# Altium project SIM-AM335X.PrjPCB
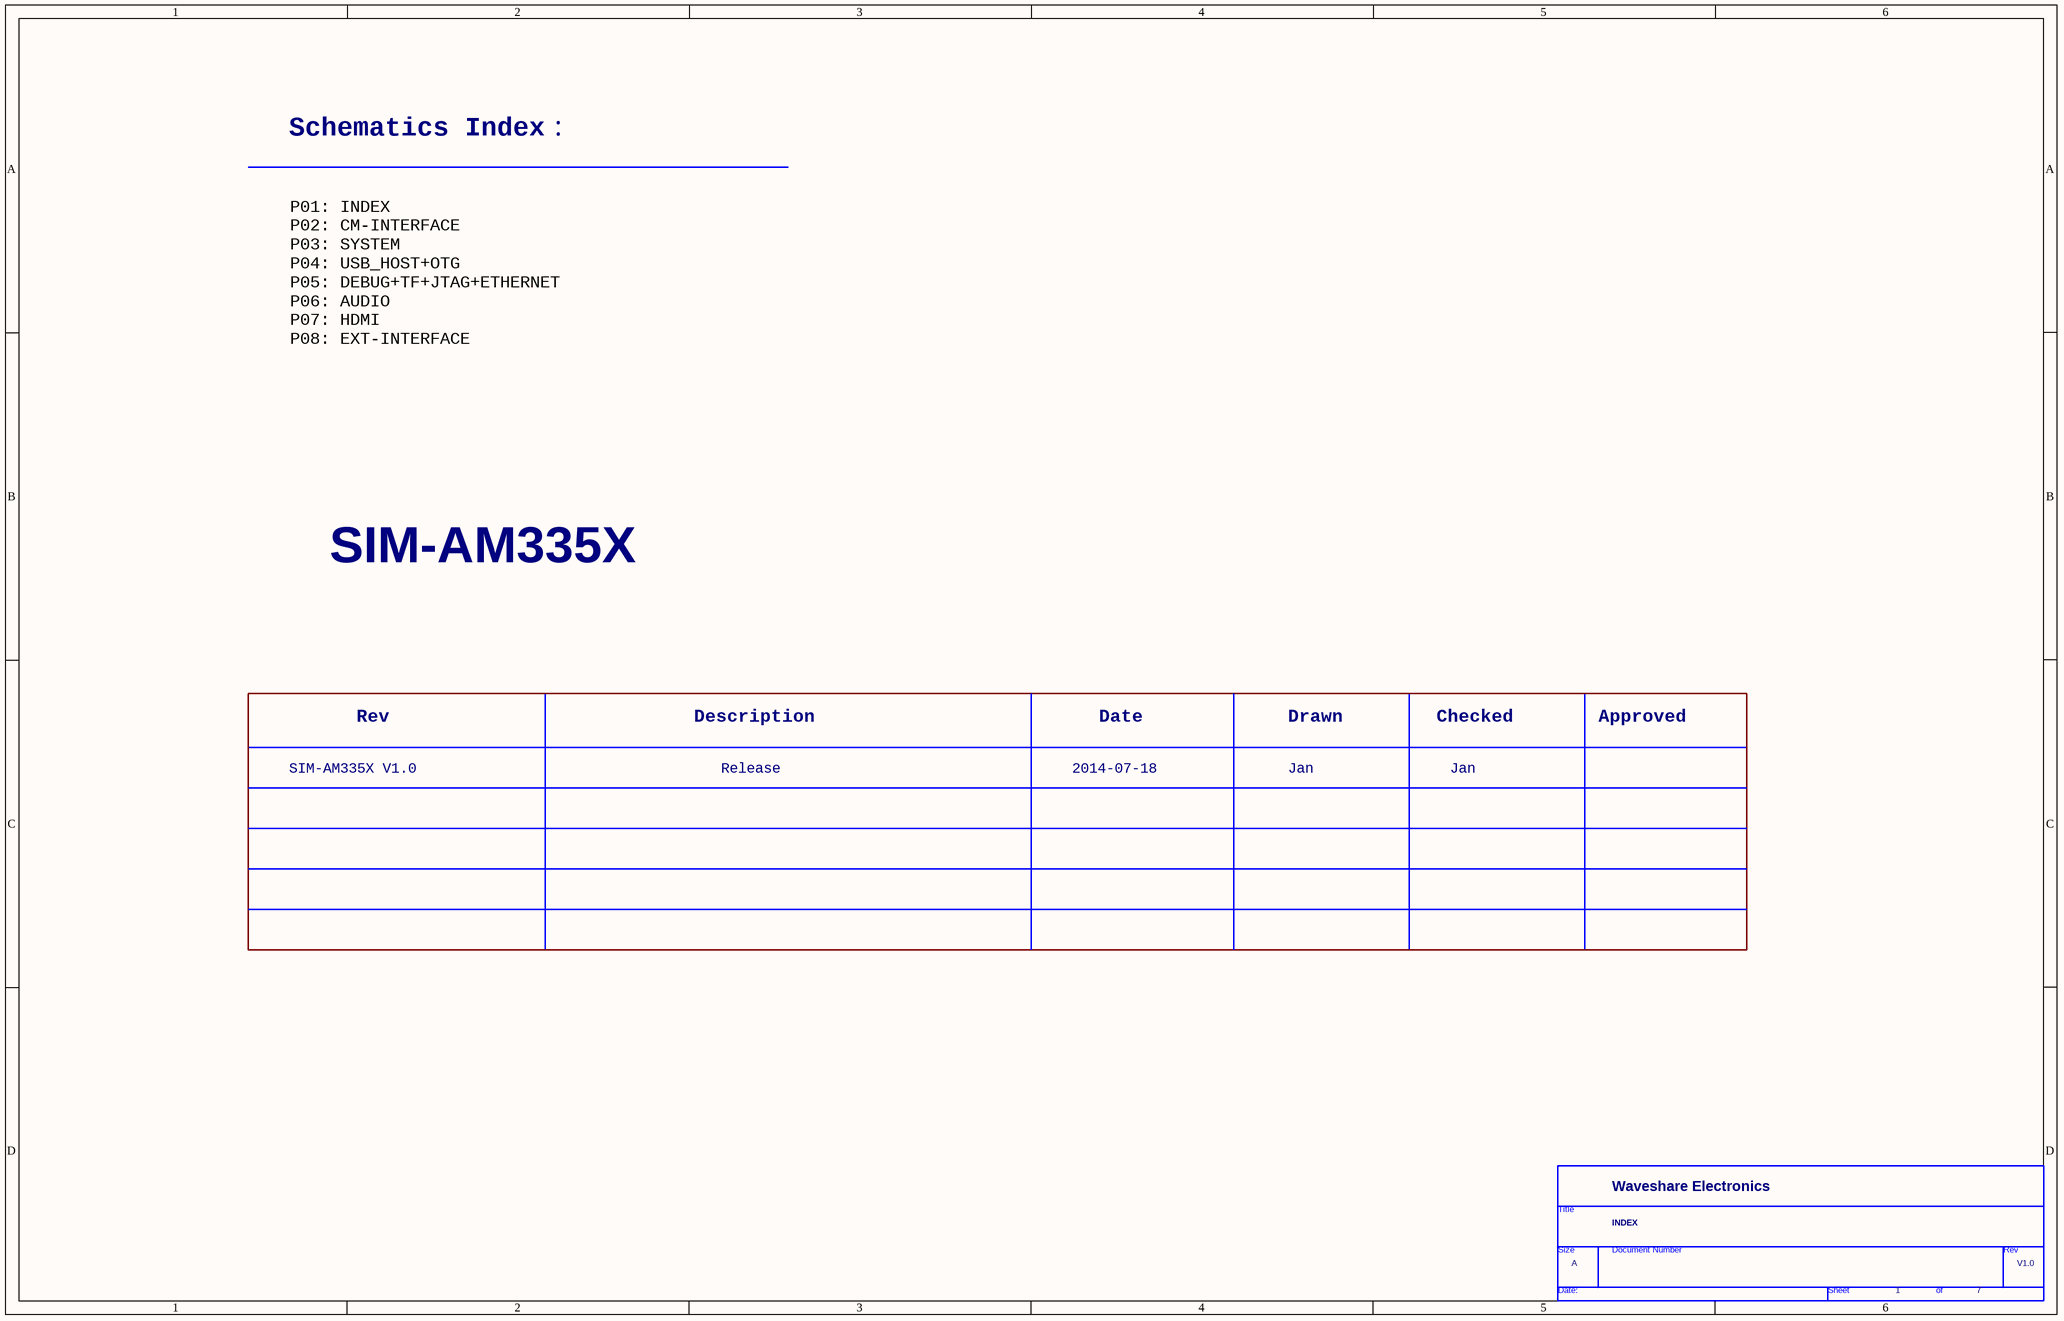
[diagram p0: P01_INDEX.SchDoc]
7 sheets, 179 parts. Net scope: global (net labels, ports and power ports of the same name join across sheets).
Board file: SIM-AM335X.PcbDoc
Sheets:
  P01_INDEX.SchDoc
  P02_CM-INTERFACE.SchDoc
  P03_SYSTEM.SchDoc
  P04_DEBUG+TF.SchDoc
  P05_USB_HOST+OTG.SchDoc
  P06_HDMI.SchDoc
  P07_EXT-INTERFACE.SchDoc

## Sheet P01_INDEX.SchDoc
size 386 x 246 mm

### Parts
(Parts that share a designator on the sheet are numbered #1, #2 ... from top to bottom, then left to right.)
*#1  Page Count: 7  Page Number: 1  Page Size: A  OrgName: Waveshare Electronics  Title: INDEX  RevCode: V1.0  (hidden comment: TitleBlock1)  (graphical)

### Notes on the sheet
- Schematics Index：
- P01: INDEX
  P02: CM-INTERFACE
  P03: SYSTEM
  P04: USB_HOST+OTG
  P05: DEBUG+TF+JTAG+ETHERNET
  P06: AUDIO
  P07: HDMI
  P08: EXT-INTERFACE
- SIM-AM335X
- Rev
- Description
- Date
- Drawn
- Checked
- Approved
- SIM-AM335X V1.0
- Release
- 2014-07-18
- Jan

## Sheet P02_CM-INTERFACE.SchDoc
size 386 x 246 mm
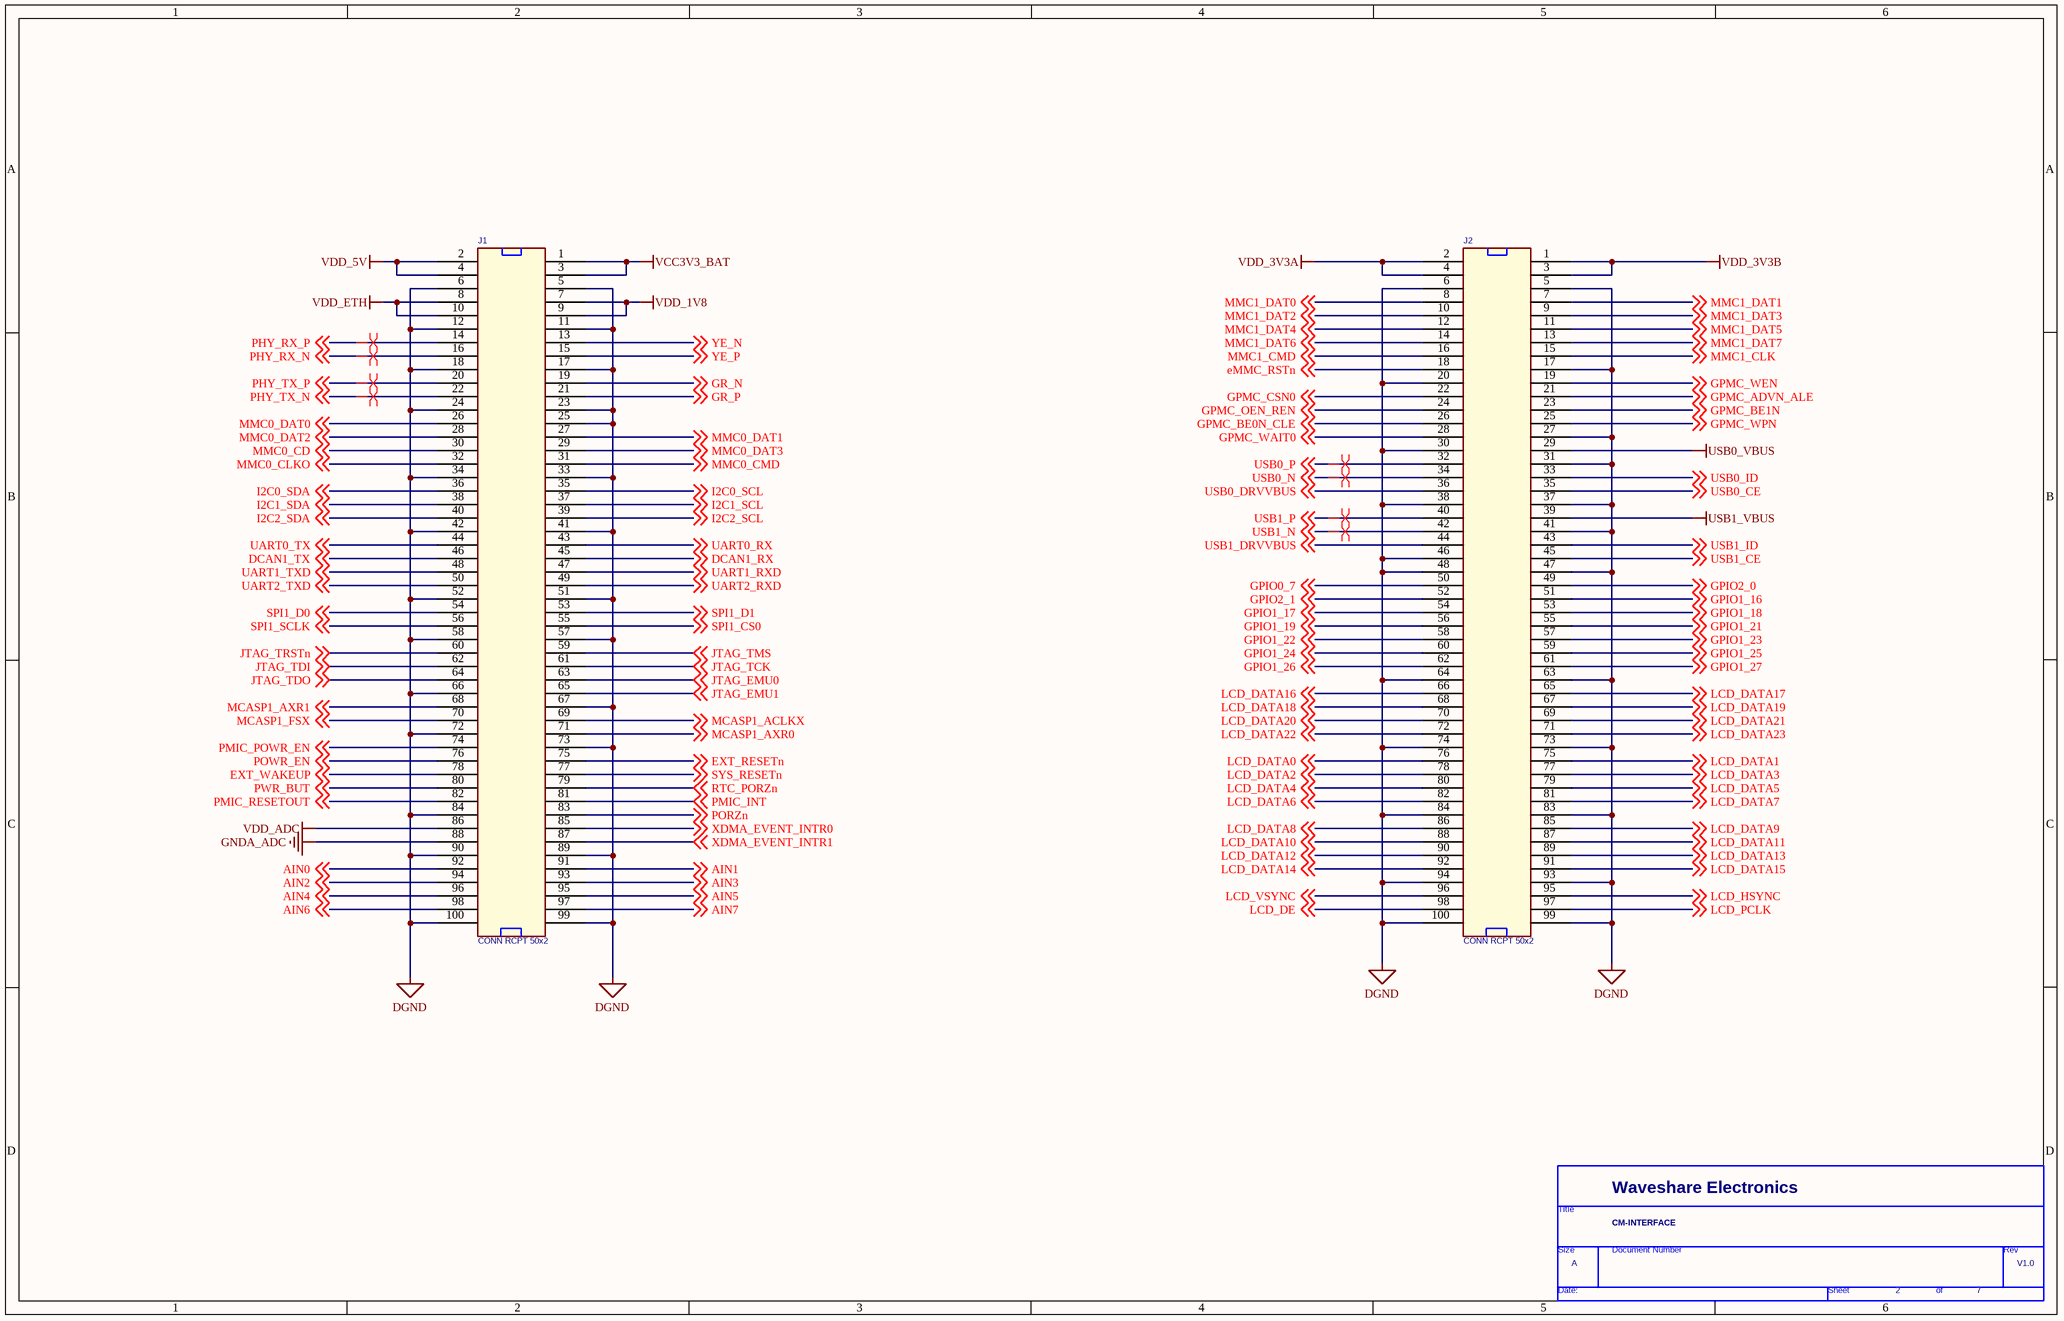
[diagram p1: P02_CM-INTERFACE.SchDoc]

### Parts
(Parts that share a designator on the sheet are numbered #1, #2 ... from top to bottom, then left to right.)
*#2  Page Count: 7  Page Number: 2  Page Size: A  OrgName: Waveshare Electronics  Title: CM-INTERFACE  RevCode: V1.0  (hidden comment: TitleBlock1)  (graphical)
J1  CONN RCPT 50x2  [SMD50X2A-1.27MM_1]
J2  CONN RCPT 50x2  [SMD50X2A-1.27MM_1]

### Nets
DGND: J1.5 J1.6 J1.11 J1.12 J1.17 J1.18 J1.23 J1.24 J1.25 J1.33 J1.34 J1.41 J1.42 J1.51 J1.52 J1.57 J1.58 J1.66 J1.67 J1.72 J1.73 J1.84 J1.89 J1.90 J1.99 J1.100 J2.5 J2.6 J2.17 J2.20 J2.27 J2.30 J2.31 J2.37 J2.38 J2.41 J2.46 J2.47 J2.48 J2.63 J2.64 J2.73 J2.74 J2.83 J2.84 J2.93 J2.94 J2.99 J2.100
GNDA_ADC: J1.88
USB0_VBUS: J2.29
USB1_VBUS: J2.39
VCC3V3_BAT: J1.1 J1.3
VDD_1V8: J1.7 J1.9
VDD_3V3A: J2.2 J2.4
VDD_3V3B: J2.1 J2.3
VDD_5V: J1.2 J1.4
VDD_ADC: J1.86
VDD_ETH: J1.8 J1.10
AIN0: J1.92 ; off-sheet AIN0
AIN1: J1.91 ; off-sheet AIN1
AIN2: J1.94 ; off-sheet AIN2
AIN3: J1.93 ; off-sheet AIN3
AIN4: J1.96 ; off-sheet AIN4
AIN5: J1.95 ; off-sheet AIN5
AIN6: J1.98 ; off-sheet AIN6
AIN7: J1.97 ; off-sheet AIN7
DCAN1_RX: J1.45 ; off-sheet DCAN1_RX
DCAN1_TX: J1.46 ; off-sheet DCAN1_TX
eMMC_RSTn: J2.18 ; off-sheet eMMC_RSTn
EXT_RESETn: J1.75 ; off-sheet EXT_RESETn
EXT_WAKEUP: J1.78 ; off-sheet EXT_WAKEUP
GPIO0_7: J2.50 ; off-sheet GPIO0_7
GPIO1_16: J2.51 ; off-sheet GPIO1_16
GPIO1_17: J2.54 ; off-sheet GPIO1_17
GPIO1_18: J2.53 ; off-sheet GPIO1_18
GPIO1_19: J2.56 ; off-sheet GPIO1_19
GPIO1_21: J2.55 ; off-sheet GPIO1_21
GPIO1_22: J2.58 ; off-sheet GPIO1_22
GPIO1_23: J2.57 ; off-sheet GPIO1_23
GPIO1_24: J2.60 ; off-sheet GPIO1_24
GPIO1_25: J2.59 ; off-sheet GPIO1_25  [project net HDMI_INT]
GPIO1_26: J2.62 ; off-sheet GPIO1_26
GPIO1_27: J2.61 ; off-sheet GPIO1_27
GPIO2_0: J2.49 ; off-sheet GPIO2_0
GPIO2_1: J2.52 ; off-sheet GPIO2_1
GPMC_ADVN_ALE: J2.21 ; off-sheet GPMC_ADVN_ALE
GPMC_BE0N_CLE: J2.26 ; off-sheet GPMC_BE0N_CLE
GPMC_BE1N: J2.23 ; off-sheet GPMC_BE1N
GPMC_CSN0: J2.22 ; off-sheet GPMC_CSN0
GPMC_OEN_REN: J2.24 ; off-sheet GPMC_OEN_REN
GPMC_WAIT0: J2.28 ; off-sheet GPMC_WAIT0
GPMC_WEN: J2.19 ; off-sheet GPMC_WEN
GPMC_WPN: J2.25 ; off-sheet GPMC_WPN
GR_N: J1.19 ; off-sheet GR_N
GR_P: J1.21 ; off-sheet GR_P
I2C0_SCL: J1.35 ; off-sheet I2C0_SCL
I2C0_SDA: J1.36 ; off-sheet I2C0_SDA
I2C1_SCL: J1.37 ; off-sheet I2C1_SCL
I2C1_SDA: J1.38 ; off-sheet I2C1_SDA
I2C2_SCL: J1.39 ; off-sheet I2C2_SCL
I2C2_SDA: J1.40 ; off-sheet I2C2_SDA
JTAG_EMU0: J1.63 ; off-sheet JTAG_EMU0
JTAG_EMU1: J1.65 ; off-sheet JTAG_EMU1
JTAG_TCK: J1.61 ; off-sheet JTAG_TCK
JTAG_TDI: J1.62 ; off-sheet JTAG_TDI
JTAG_TDO: J1.64 ; off-sheet JTAG_TDO
JTAG_TMS: J1.59 ; off-sheet JTAG_TMS
JTAG_TRSTn: J1.60 ; off-sheet JTAG_TRSTn
LCD_DATA0: J2.76 ; off-sheet LCD_DATA0
LCD_DATA1: J2.75 ; off-sheet LCD_DATA1
LCD_DATA2: J2.78 ; off-sheet LCD_DATA2
LCD_DATA3: J2.77 ; off-sheet LCD_DATA3
LCD_DATA4: J2.80 ; off-sheet LCD_DATA4
LCD_DATA5: J2.79 ; off-sheet LCD_DATA5
LCD_DATA6: J2.82 ; off-sheet LCD_DATA6
LCD_DATA7: J2.81 ; off-sheet LCD_DATA7
LCD_DATA8: J2.86 ; off-sheet LCD_DATA8
LCD_DATA9: J2.85 ; off-sheet LCD_DATA9
LCD_DATA10: J2.88 ; off-sheet LCD_DATA10
LCD_DATA11: J2.87 ; off-sheet LCD_DATA11
LCD_DATA12: J2.90 ; off-sheet LCD_DATA12
LCD_DATA13: J2.89 ; off-sheet LCD_DATA13
LCD_DATA14: J2.92 ; off-sheet LCD_DATA14
LCD_DATA15: J2.91 ; off-sheet LCD_DATA15
LCD_DATA16: J2.66 ; off-sheet LCD_DATA16
LCD_DATA17: J2.65 ; off-sheet LCD_DATA17
LCD_DATA18: J2.68 ; off-sheet LCD_DATA18
LCD_DATA19: J2.67 ; off-sheet LCD_DATA19
LCD_DATA20: J2.70 ; off-sheet LCD_DATA20
LCD_DATA21: J2.69 ; off-sheet LCD_DATA21
LCD_DATA22: J2.72 ; off-sheet LCD_DATA22
LCD_DATA23: J2.71 ; off-sheet LCD_DATA23
LCD_DE: J2.98 ; off-sheet LCD_DE
LCD_HSYNC: J2.95 ; off-sheet LCD_HSYNC
LCD_PCLK: J2.97 ; off-sheet LCD_PCLK
LCD_VSYNC: J2.96 ; off-sheet LCD_VSYNC
MCASP1_ACLKX: J1.69 ; off-sheet MCASP1_ACLKX
MCASP1_AXR0: J1.71 ; off-sheet MCASP1_AXR0
MCASP1_AXR1: J1.68 ; off-sheet MCASP1_AXR1
MCASP1_FSX: J1.70 ; off-sheet MCASP1_FSX
MMC0_CD: J1.30 ; off-sheet MMC0_CD
MMC0_CLKO: J1.32 ; off-sheet MMC0_CLKO
MMC0_CMD: J1.31 ; off-sheet MMC0_CMD
MMC0_DAT0: J1.26 ; off-sheet MMC0_DAT0
MMC0_DAT1: J1.27 ; off-sheet MMC0_DAT1
MMC0_DAT2: J1.28 ; off-sheet MMC0_DAT2
MMC0_DAT3: J1.29 ; off-sheet MMC0_DAT3
MMC1_CLK: J2.15 ; off-sheet MMC1_CLK
MMC1_CMD: J2.16 ; off-sheet MMC1_CMD
MMC1_DAT0: J2.8 ; off-sheet MMC1_DAT0
MMC1_DAT1: J2.7 ; off-sheet MMC1_DAT1
MMC1_DAT2: J2.10 ; off-sheet MMC1_DAT2
MMC1_DAT3: J2.9 ; off-sheet MMC1_DAT3
MMC1_DAT4: J2.12 ; off-sheet MMC1_DAT4
MMC1_DAT5: J2.11 ; off-sheet MMC1_DAT5
MMC1_DAT6: J2.14 ; off-sheet MMC1_DAT6
MMC1_DAT7: J2.13 ; off-sheet MMC1_DAT7
PHY_RX_N: J1.16 ; off-sheet PHY_RX_N
PHY_RX_P: J1.14 ; off-sheet PHY_RX_P
PHY_TX_N: J1.22 ; off-sheet PHY_TX_N
PHY_TX_P: J1.20 ; off-sheet PHY_TX_P
PMIC_INT: J1.81 ; off-sheet PMIC_INT
PMIC_POWR_EN: J1.74 ; off-sheet PMIC_POWR_EN
PMIC_RESETOUT: J1.82 ; off-sheet PMIC_RESETOUT
PORZn: J1.83 ; off-sheet PORZn
POWR_EN: J1.76 ; off-sheet POWR_EN
PWR_BUT: J1.80 ; off-sheet PWR_BUT
RTC_PORZn: J1.79 ; off-sheet RTC_PORZn
SPI1_CS0: J1.55 ; off-sheet SPI1_CS0
SPI1_D0: J1.54 ; off-sheet SPI1_D0
SPI1_D1: J1.53 ; off-sheet SPI1_D1
SPI1_SCLK: J1.56 ; off-sheet SPI1_SCLK
SYS_RESETn: J1.77 ; off-sheet SYS_RESETn
UART0_RX: J1.43 ; off-sheet UART0_RX
UART0_TX: J1.44 ; off-sheet UART0_TX
UART1_RXD: J1.47 ; off-sheet UART1_RXD
UART1_TXD: J1.48 ; off-sheet UART1_TXD
UART2_RXD: J1.49 ; off-sheet UART2_RXD
UART2_TXD: J1.50 ; off-sheet UART2_TXD
USB0_CE: J2.35 ; off-sheet USB0_CE
USB0_DRVVBUS: J2.36 ; off-sheet USB0_DRVVBUS
USB0_ID: J2.33 ; off-sheet USB0_ID
USB0_N: J2.34 ; off-sheet USB0_N
USB0_P: J2.32 ; off-sheet USB0_P
USB1_CE: J2.45 ; off-sheet USB1_CE
USB1_DRVVBUS: J2.44 ; off-sheet USB1_DRVVBUS
USB1_ID: J2.43 ; off-sheet USB1_ID
USB1_N: J2.42 ; off-sheet USB1_N
USB1_P: J2.40 ; off-sheet USB1_P
XDMA_EVENT_INTR0: J1.85 ; off-sheet XDMA_EVENT_INTR0
XDMA_EVENT_INTR1: J1.87 ; off-sheet XDMA_EVENT_INTR1
YE_N: J1.13 ; off-sheet YE_N
YE_P: J1.15 ; off-sheet YE_P

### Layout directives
differential pair: PHY_RX_N, PHY_RX_P, PHY_TX_N, PHY_TX_P, USB0_N, USB0_P, USB1_N, USB1_P

## Sheet P03_SYSTEM.SchDoc
size 386 x 246 mm
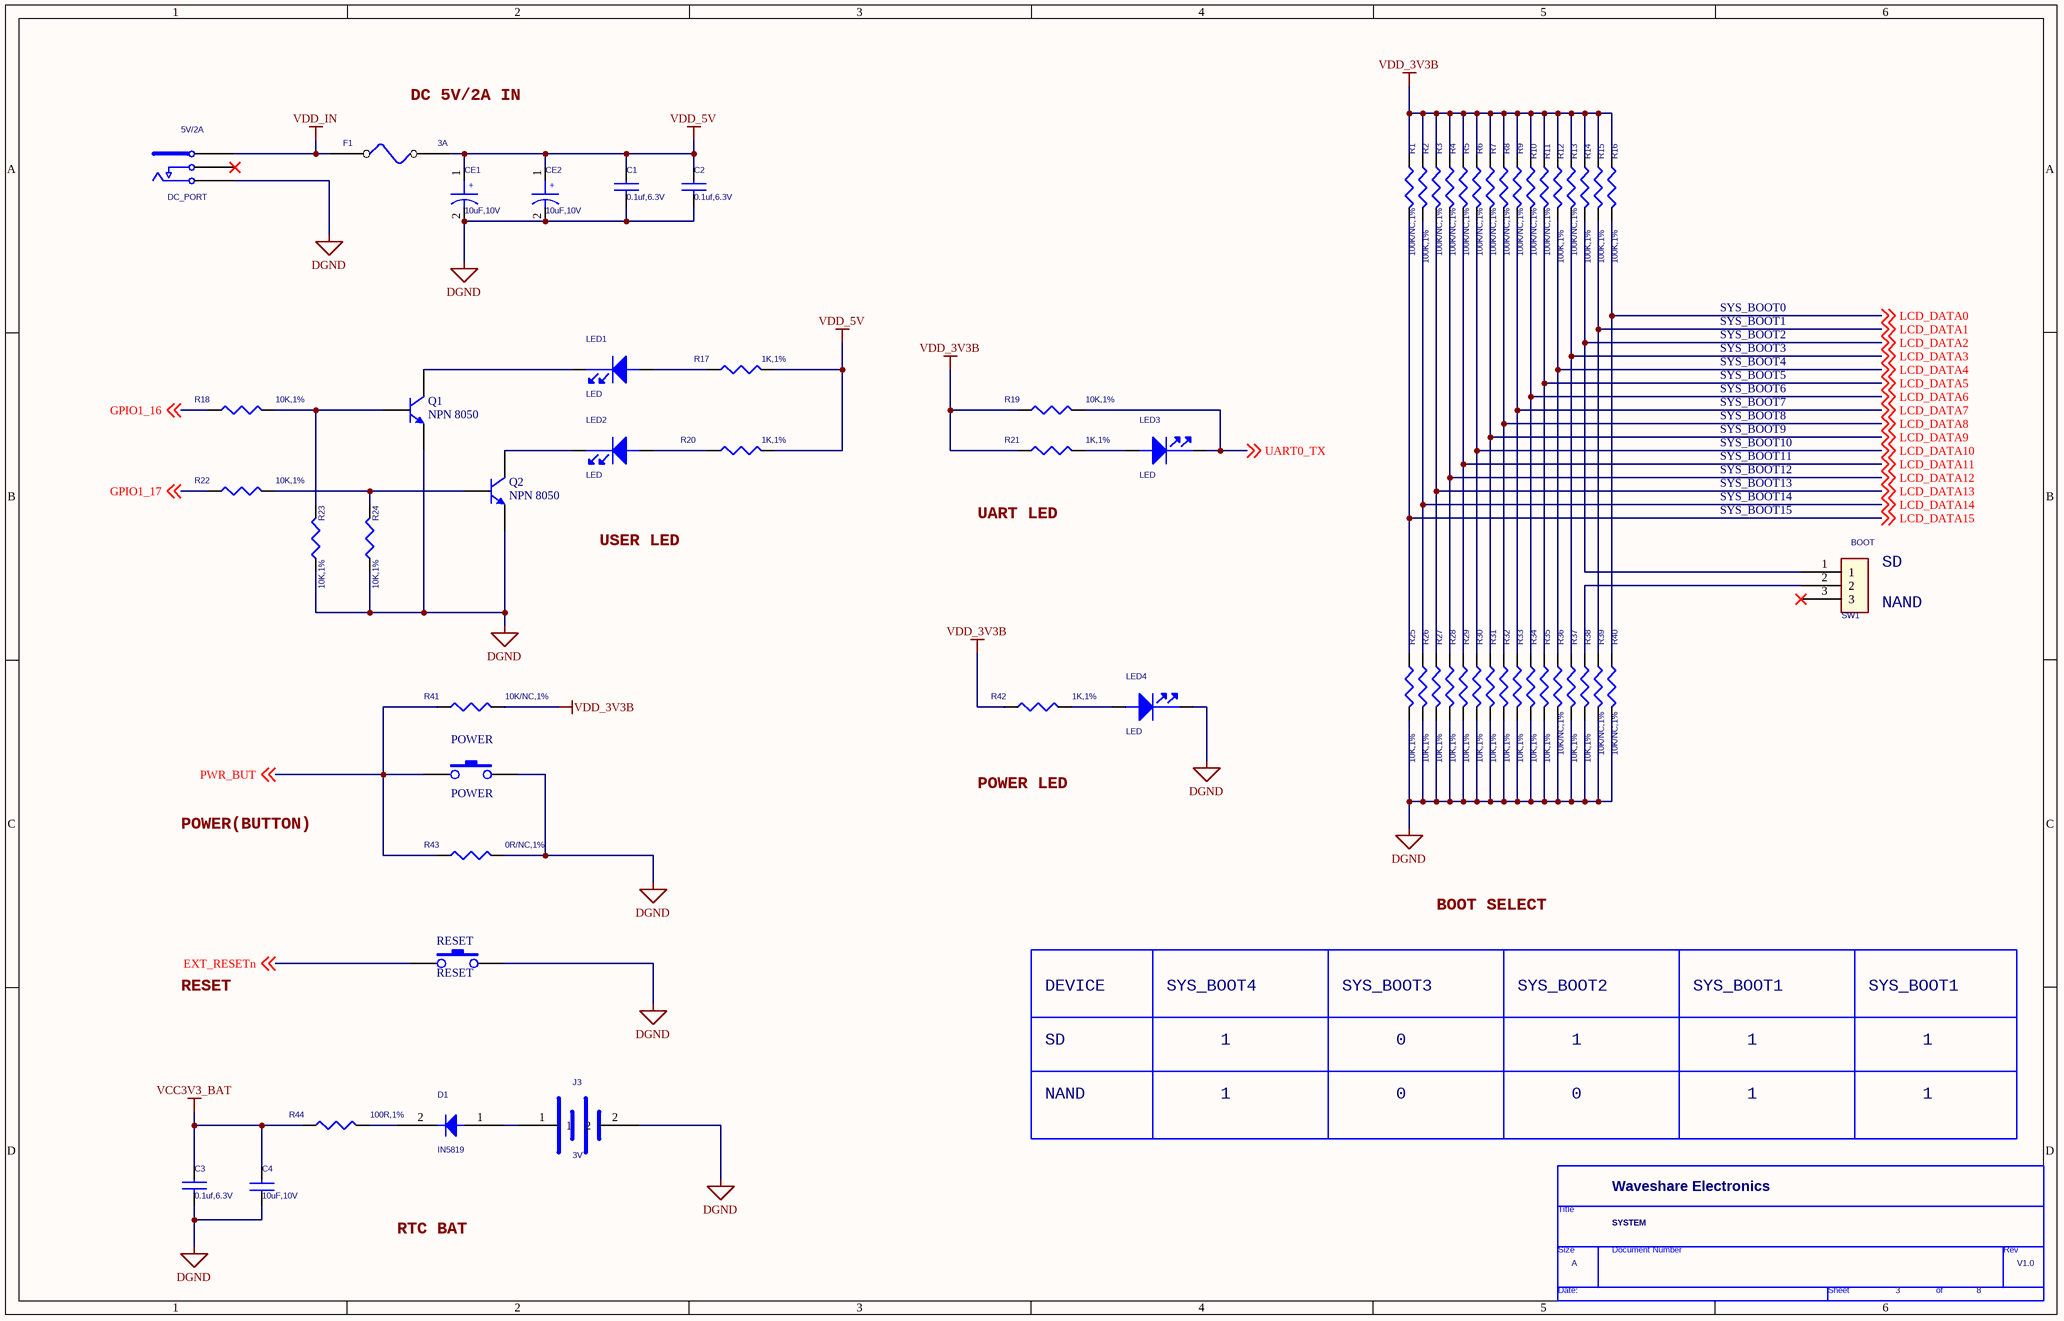
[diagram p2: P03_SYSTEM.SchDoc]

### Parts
(Parts that share a designator on the sheet are numbered #1, #2 ... from top to bottom, then left to right.)
5V/2A  DC_PORT  [DC3-3.5]
*#3  Page Count: 8  Page Number: 3  Page Size: A  OrgName: Waveshare Electronics  Title: SYSTEM  RevCode: V1.0  (hidden comment: TitleBlock1)  (graphical)
BOOT  SW1  [SWITCH_1]
C1  0.1uf,6.3V  [C0805]
C2  0.1uf,6.3V  [C0805]
C3  0.1uf,6.3V  [C0603]
C4  10uF,10V  [C0805]
CE1  10uF,10V  [C1206_A]
CE2  10uF,10V  [C1206_A]
D1  IN5819  [DO_214AC]
F1  3A  [F1206]
J3  3V  [CR1220]
LED1  LED  [LED0603]
LED2  LED  [LED0603]
LED3  LED  [LED0603]
LED4  LED  [LED0603]
POWER  POWER  [KEY_5]
Q1  NPN 8050  [SOT-23]
Q2  NPN 8050  [SOT-23]
R1  100K/NC,1%  [R0402]
R2  100K,1%  [R0402]
R3  100K/NC,1%  [R0402]
R4  100K/NC,1%  [R0402]
R5  100K/NC,1%  [R0402]
R6  100K/NC,1%  [R0402]
R7  100K/NC,1%  [R0402]
R8  100K/NC,1%  [R0402]
R9  100K/NC,1%  [R0402]
R10  100K/NC,1%  [R0402]
R11  100K/NC,1%  [R0402]
R12  100K,1%  [R0402]
R13  100K/NC,1%  [R0402]
R14  100K,1%  [R0402]
R15  100K,1%  [R0402]
R16  100K,1%  [R0402]
R17  1K,1%  [R0402]
R18  10K,1%  [R0402]
R19  10K,1%  [R0402]
R20  1K,1%  [R0402]
R21  1K,1%  [R0402]
R22  10K,1%  [R0402]
R23  10K,1%  [R0402]
R24  10K,1%  [R0402]
R25  10K,1%  [R0402]
R26  10K,1%  [R0402]
R27  10K,1%  [R0402]
R28  10K,1%  [R0402]
R29  10K,1%  [R0402]
R30  10K,1%  [R0402]
R31  10K,1%  [R0402]
R32  10K,1%  [R0402]
R33  10K,1%  [R0402]
R34  10K,1%  [R0402]
R35  10K,1%  [R0402]
R36  10K/NC,1%  [R0402]
R37  10K,1%  [R0402]
R38  10K,1%  [R0402]
R39  10K/NC,1%  [R0402]
R40  10K/NC,1%  [R0402]
R41  10K/NC,1%  [R0402]
R42  1K,1%  [R0402]
R43  0R/NC,1%  [R0402]
R44  100R,1%  [R0603]
RESET  RESET  [KEY_5]

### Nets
DGND: 5V/2A.3 C1.2 C2.2 C3.2 C4.1 CE1.2 CE2.2 J3.2 LED4.2(CATHODE) POWER.2 Q1.2(E) Q2.2(E) R23.1 R24.1 R25.2 R26.2 R27.2 R28.2 R29.2 R30.2 R31.2 R32.2 R33.2 R34.2 R35.2 R36.2 R37.2 R38.2 R39.2 R40.2 R43.2 RESET.2
VCC3V3_BAT: C3.1 C4.2 R44.1
VDD_3V3B: R1.1 R2.1 R3.1 R4.1 R5.1 R6.1 R7.1 R8.1 R9.1 R10.1 R11.1 R12.1 R13.1 R14.1 R15.1 R16.1 R19.1 R21.1 R41.2 R42.1
VDD_5V: C1.1 C2.1 CE1.1 CE2.1 F1.2 R17.2 R20.2
VDD_IN: 5V/2A.1 F1.1
EXT_RESETn: RESET.1 ; off-sheet EXT_RESETn
GPIO1_16: R18.1 ; off-sheet GPIO1_16
GPIO1_17: R22.1 ; off-sheet GPIO1_17
LCD_DATA0: R16.2 R40.1 ; off-sheet LCD_DATA0
LCD_DATA1: R15.2 R39.1 ; off-sheet LCD_DATA1
LCD_DATA2: BOOT.1 R14.2 ; off-sheet LCD_DATA2
LCD_DATA3: R13.2 R37.1 ; off-sheet LCD_DATA3
LCD_DATA4: R12.2 R36.1 ; off-sheet LCD_DATA4
LCD_DATA5: R11.2 R35.1 ; off-sheet LCD_DATA5
LCD_DATA6: R10.2 R34.1 ; off-sheet LCD_DATA6
LCD_DATA7: R9.2 R33.1 ; off-sheet LCD_DATA7
LCD_DATA8: R8.2 R32.1 ; off-sheet LCD_DATA8
LCD_DATA9: R7.2 R31.1 ; off-sheet LCD_DATA9
LCD_DATA10: R6.2 R30.1 ; off-sheet LCD_DATA10
LCD_DATA11: R5.2 R29.1 ; off-sheet LCD_DATA11
LCD_DATA12: R4.2 R28.1 ; off-sheet LCD_DATA12
LCD_DATA13: R3.2 R27.1 ; off-sheet LCD_DATA13
LCD_DATA14: R2.2 R26.1 ; off-sheet LCD_DATA14
LCD_DATA15: R1.2 R25.1 ; off-sheet LCD_DATA15
PWR_BUT: POWER.1 R41.1 R43.1 ; off-sheet PWR_BUT
UART0_TX: LED3.2(CATHODE) R19.2 ; off-sheet UART0_TX
NetBOOT_2: BOOT.2 R38.1
NetD1_1: D1.1 J3.1
NetD1_2: D1.2 R44.2
NetLED1_1: LED1.1(ANODE) R17.1
NetLED1_2: LED1.2(CATHODE) Q1.3(C)
NetLED2_1: LED2.1(ANODE) R20.1
NetLED2_2: LED2.2(CATHODE) Q2.3(C)
NetLED3_1: LED3.1(ANODE) R21.2
NetLED4_1: LED4.1(ANODE) R42.2
NetQ1_1: Q1.1(B) R18.2 R23.2
NetQ2_1: Q2.1(B) R22.2 R24.2

Not connected (* = marked no-connect by the designer): 5V/2A 2*; BOOT 3*

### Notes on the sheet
- DC 5V/2A IN
- SYS_BOOT0
- SYS_BOOT1
- SYS_BOOT2
- SYS_BOOT3
- SYS_BOOT4
- SYS_BOOT5
- SYS_BOOT6
- SYS_BOOT7
- SYS_BOOT8
- SYS_BOOT9
- SYS_BOOT10
- SYS_BOOT11
- UART LED
- SYS_BOOT12
- SYS_BOOT13
- SYS_BOOT14
- SYS_BOOT15
- USER LED
- (near BOOT) SD
- (near BOOT) NAND
- POWER LED
- POWER(BUTTON)
- BOOT SELECT
- RESET
- DEVICE
- SD
- 1
- 0
- NAND
- RTC BAT

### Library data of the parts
5V/2A = DC_0
C1-C3 = CAP_0.1uF_X5R_6.3V_20% 0201: Part Number: CAP_0.1uf_X7R_16V_10%_0402; Desc: Capacitor 0.01uF 16V 10% 0402
C4 = CAP_10uF_Y5V_10V_10%_0805: Desc: CAP CER 10UF 10V Y5V 0805
CE1 CE2 = CD6.3/2.5
F1 = FUSE
J3 = BATERY
POWER RESET = KEY
Q1 Q2 = NPN_SOT23
R1-R16 R25-R40 = RES_100K_1/16W_1%_0402: Resistor 100Kohm 1/16W 1% 0402
R17-R24 R41-R44 = RES_4.75K_1/16W_1%_0402: RES 4.75K OHM 1/16W 1% 0402 SMD

## Sheet P04_DEBUG+TF.SchDoc
size 386 x 246 mm
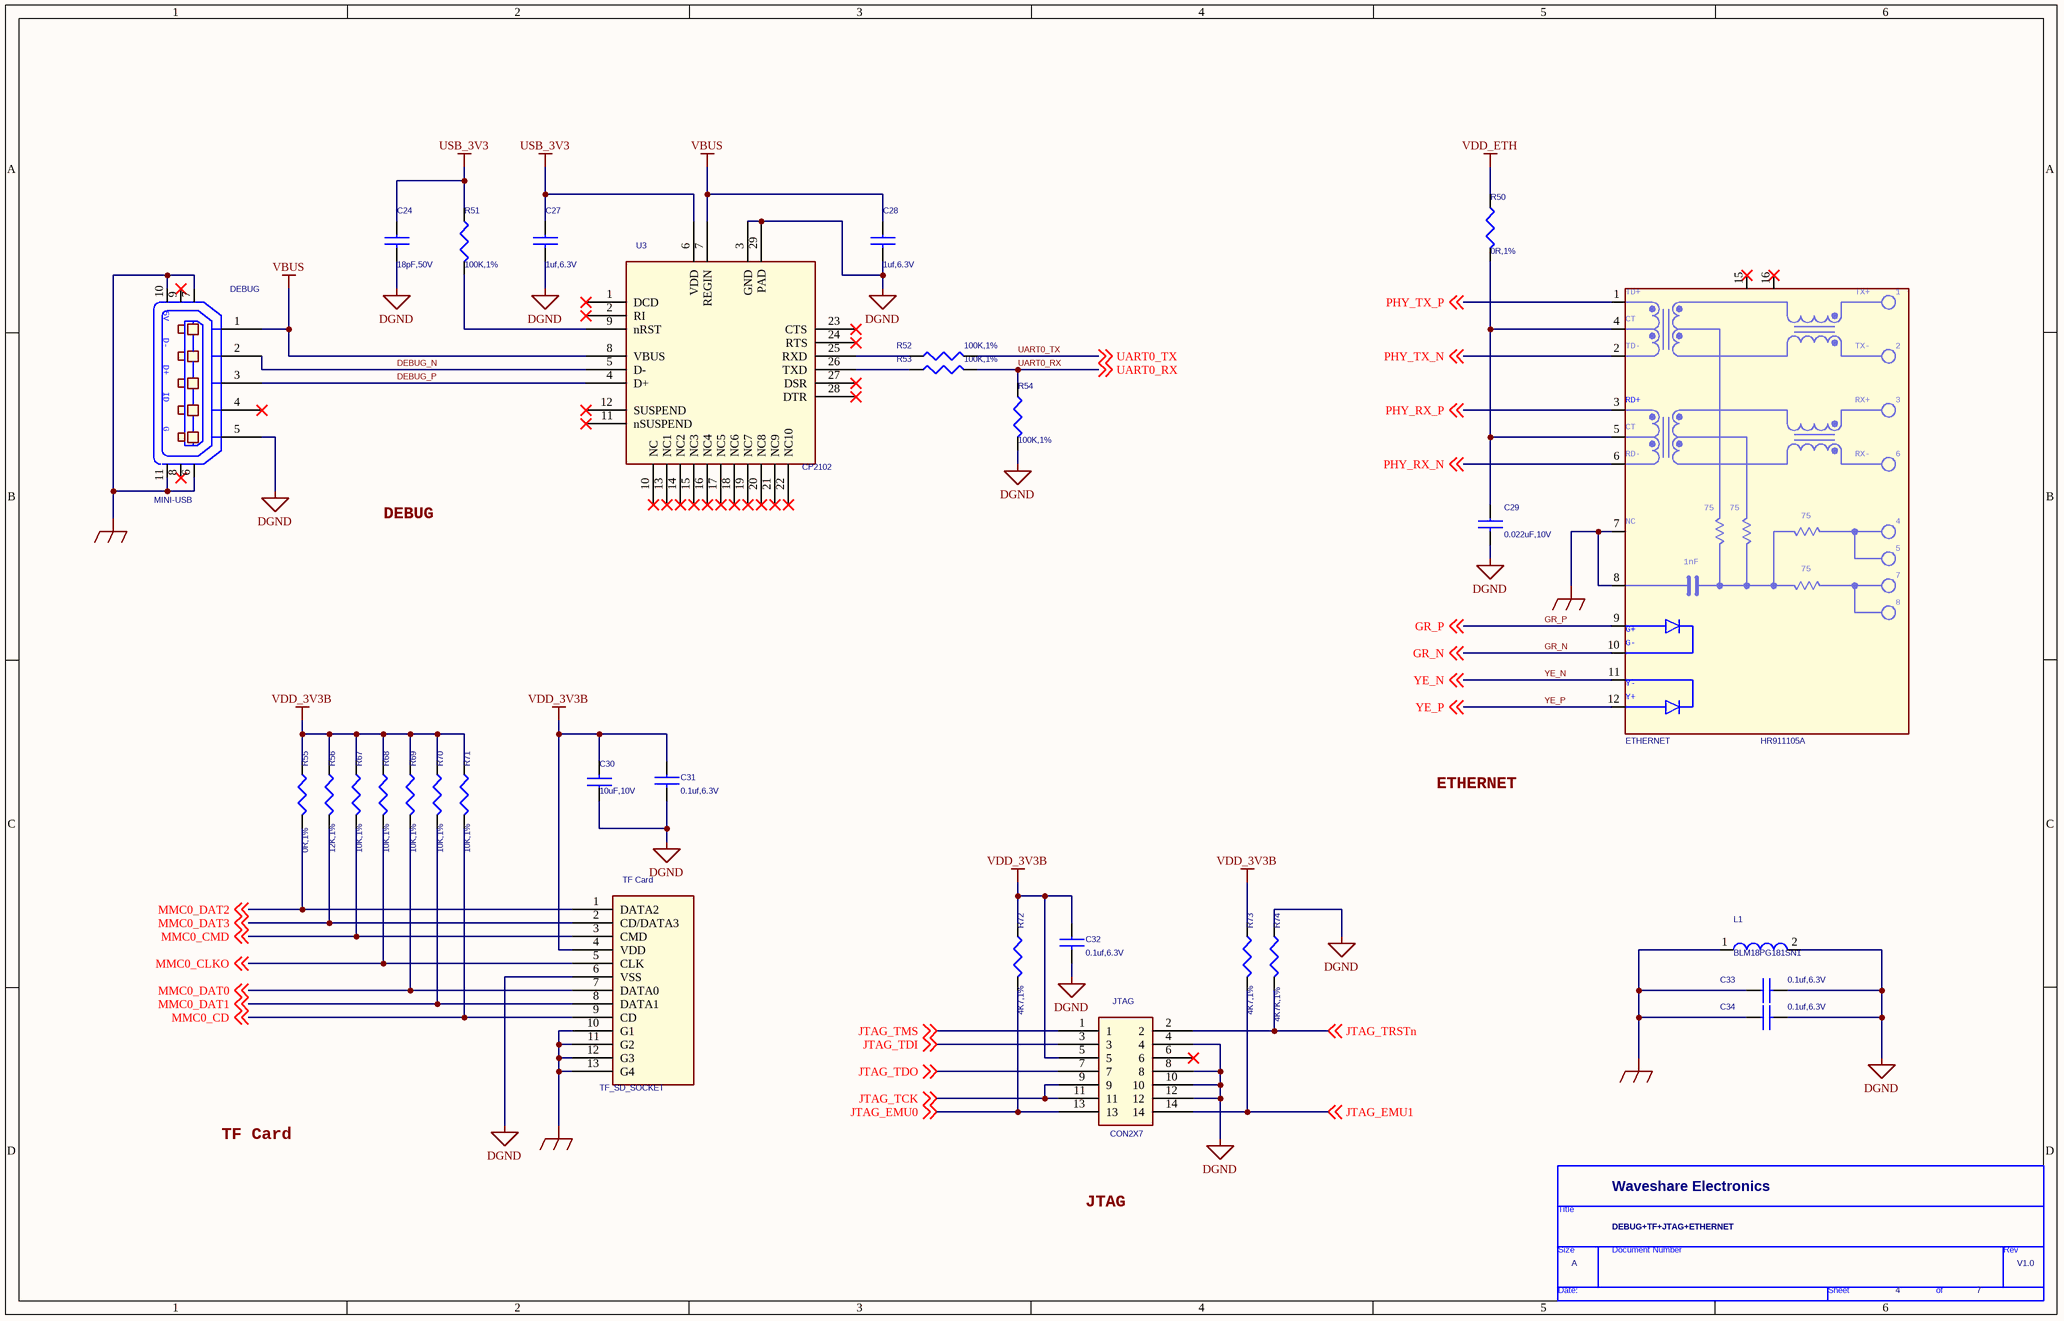
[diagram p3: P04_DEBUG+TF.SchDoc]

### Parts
(Parts that share a designator on the sheet are numbered #1, #2 ... from top to bottom, then left to right.)
*#4  Page Count: 7  Page Number: 4  Page Size: A  OrgName: Waveshare Electronics  Title: DEBUG+TF+JTAG+ETHERNET  RevCode: V1.0  (hidden comment: TitleBlock1)  (graphical)
C24  18pF,50V  [C0402]
C27  1uf,6.3V  [0402]
C28  1uf,6.3V  [C0402]
C29  0.022uF,10V  [C0402]
C30  10uF,10V  [C0603]
C31  0.1uf,6.3V  [C0402]
C32  0.1uf,6.3V  [C0402]
C33  0.1uf,6.3V  [C0402]
C34  0.1uf,6.3V  [C0402]
DEBUG  VAL: MINI-USB  [USB2]  (hidden comment: USB MICRO B Connector)
ETHERNET  HR911105A  [HY911105H]
JTAG  CON2X7  [HEADER 7X2-2MM-SMT]
L1  BLM18PG181SN1  [L0603]
R50  0R,1%  [R0402]
R51  100K,1%  [R0402]
R52  100K,1%  [R0402]
R53  100K,1%  [R0402]
R54  100K,1%  [R0402]
R55  0R,1%  [R0402]
R56  12K,1%  [R0402]
R67  10K,1%  [R0402]
R68  10K,1%  [R0402]
R69  10K,1%  [R0402]
R70  10K,1%  [R0402]
R71  10K,1%  [R0402]
R72  4K7,1%  [R0402]
R73  4K7,1%  [R0402]
R74  4K7K,1%  [R0402]
TF_Card  TF_SD_SOCKET  [TF-CARD9]
U3  CP2102  [QFN28(5x5)]

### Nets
DGND: C24.2 C27.2 C28.2 C29.2 C30.1 C31.2 C32.2 C33.2 C34.2 DEBUG.5(P5) JTAG.4 JTAG.8 JTAG.10 JTAG.12 L1.2 R54.2 R74.1 TF_Card.6(VSS) U3.3(GND) U3.29(PAD)
GND_EARTH: C33.1 C34.1 DEBUG.6(SHLD1) DEBUG.7(SHLD2) DEBUG.10(SHLD5) DEBUG.11(SHLD6) ETHERNET.7(P7) ETHERNET.8(P8) L1.1 TF_Card.10(G1) TF_Card.11(G2) TF_Card.12(G3) TF_Card.13(G4)
USB_3V3: C24.1 C27.1 R51.1 U3.6(VDD)
VBUS: C28.1 DEBUG.1(P1) U3.7(REGIN) U3.8(VBUS)
VDD_3V3B: C30.2 C31.1 C32.1 JTAG.5 R55.1 R56.1 R67.1 R68.1 R69.1 R70.1 R71.1 R72.1 R73.1 TF_Card.4(VDD)
VDD_ETH: R50.1
DEBUG_N: DEBUG.2(P2) U3.5(D-)
DEBUG_P: DEBUG.3(P3) U3.4(D+)
GR_N: ETHERNET.10(G-) ; off-sheet GR_N
GR_P: ETHERNET.9(G+) ; off-sheet GR_P
JTAG_EMU0: JTAG.13 R72.2 ; off-sheet JTAG_EMU0
JTAG_EMU1: JTAG.14 R73.2 ; off-sheet JTAG_EMU1
JTAG_TCK: JTAG.9 JTAG.11 ; off-sheet JTAG_TCK
JTAG_TDI: JTAG.3 ; off-sheet JTAG_TDI
JTAG_TDO: JTAG.7 ; off-sheet JTAG_TDO
JTAG_TMS: JTAG.1 ; off-sheet JTAG_TMS
JTAG_TRSTn: JTAG.2 R74.2 ; off-sheet JTAG_TRSTn
MMC0_CD: R71.2 TF_Card.9(CD) ; off-sheet MMC0_CD
MMC0_CLKO: R68.2 TF_Card.5(CLK) ; off-sheet MMC0_CLKO
MMC0_CMD: R67.2 TF_Card.3(CMD) ; off-sheet MMC0_CMD
MMC0_DAT0: R69.2 TF_Card.7(DATA0) ; off-sheet MMC0_DAT0
MMC0_DAT1: R70.2 TF_Card.8(DATA1) ; off-sheet MMC0_DAT1
MMC0_DAT2: R55.2 TF_Card.1(DATA2) ; off-sheet MMC0_DAT2
MMC0_DAT3: R56.2 TF_Card.2(CD/DATA3) ; off-sheet MMC0_DAT3
PHY_RX_N: ETHERNET.6(P6) ; off-sheet PHY_RX_N
PHY_RX_P: ETHERNET.3(P3) ; off-sheet PHY_RX_P
PHY_TX_N: ETHERNET.2(P2) ; off-sheet PHY_TX_N
PHY_TX_P: ETHERNET.1(P1) ; off-sheet PHY_TX_P
UART0_RX: R53.2 R54.1 ; off-sheet UART0_RX
UART0_TX: R52.2 ; off-sheet UART0_TX
YE_N: ETHERNET.11(Y-) ; off-sheet YE_N
YE_P: ETHERNET.12(Y+) ; off-sheet YE_P
NetC29_1: C29.1 ETHERNET.4(P4) ETHERNET.5(P5) R50.2
NetR51_2: R51.2 U3.9(nRST)
NetR52_1: R52.1 U3.25(RXD)
NetR53_1: R53.1 U3.26(TXD)

Not connected (* = marked no-connect by the designer): DEBUG 4(P4)* 8(SHLD3)* 9(SHLD4)*; ETHERNET 15(P15)* 16(P16)*; JTAG 6*; U3 1(DCD)* 2(RI)* 10(NC)* 11(nSUSPEND)* 12(SUSPEND)* 13(NC1)* 14(NC2)* 15(NC3)* 16(NC4)* 17(NC5)* 18(NC6)* 19(NC7)* 20(NC8)* 21(NC9)* 22(NC10)* 23(CTS)* 24(RTS)* 27(DSR)* 28(DTR)*

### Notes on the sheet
- DEBUG
- ETHERNET
- TF Card
- JTAG

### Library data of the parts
C24 C27 C28 C31-C34 = CAP_0.1uF_X5R_6.3V_20% 0201: as C1 on sheet P03_SYSTEM
C29 = CAP_0402_0.1uf_X5R_10V: Desc: CAP, CER, X7R, 0402, 10V, 10%, 0.1uF
C30 = CAP_10uF_Y5V_10V_10%_0805: Desc: CAP CER 10UF 10V Y5V 0805
DEBUG = USB MICRO B Connector: CONN MICRO_B SMT AU; REF: 56579-0578; FAB: MOLEX; DEVICE: USB_MICRO_B_RECEPTACLE
ETHERNET = J00-0061 PULSE_0: DEV: CON_PULSE_J00-61; FAB: PULSE; BOI: RJ45; DESIG: 10/100 base TX LXT971A
L1 = INDUCTOR: Part number: SM01V00480I; Vendor: TAITECH; Type: SMD
R50 R51 R54-R56 R67-R74 = RES_100K_1/16W_1%_0402: Resistor 100Kohm 1/16W 1% 0402
R52 R53 = RES_10K_1/16W_1%_0402: Resistor 10Kohm 1/16W 1% 0402
TF_Card = SD_SOCKET_0

## Sheet P05_USB_HOST+OTG.SchDoc
size 350 x 320 mm
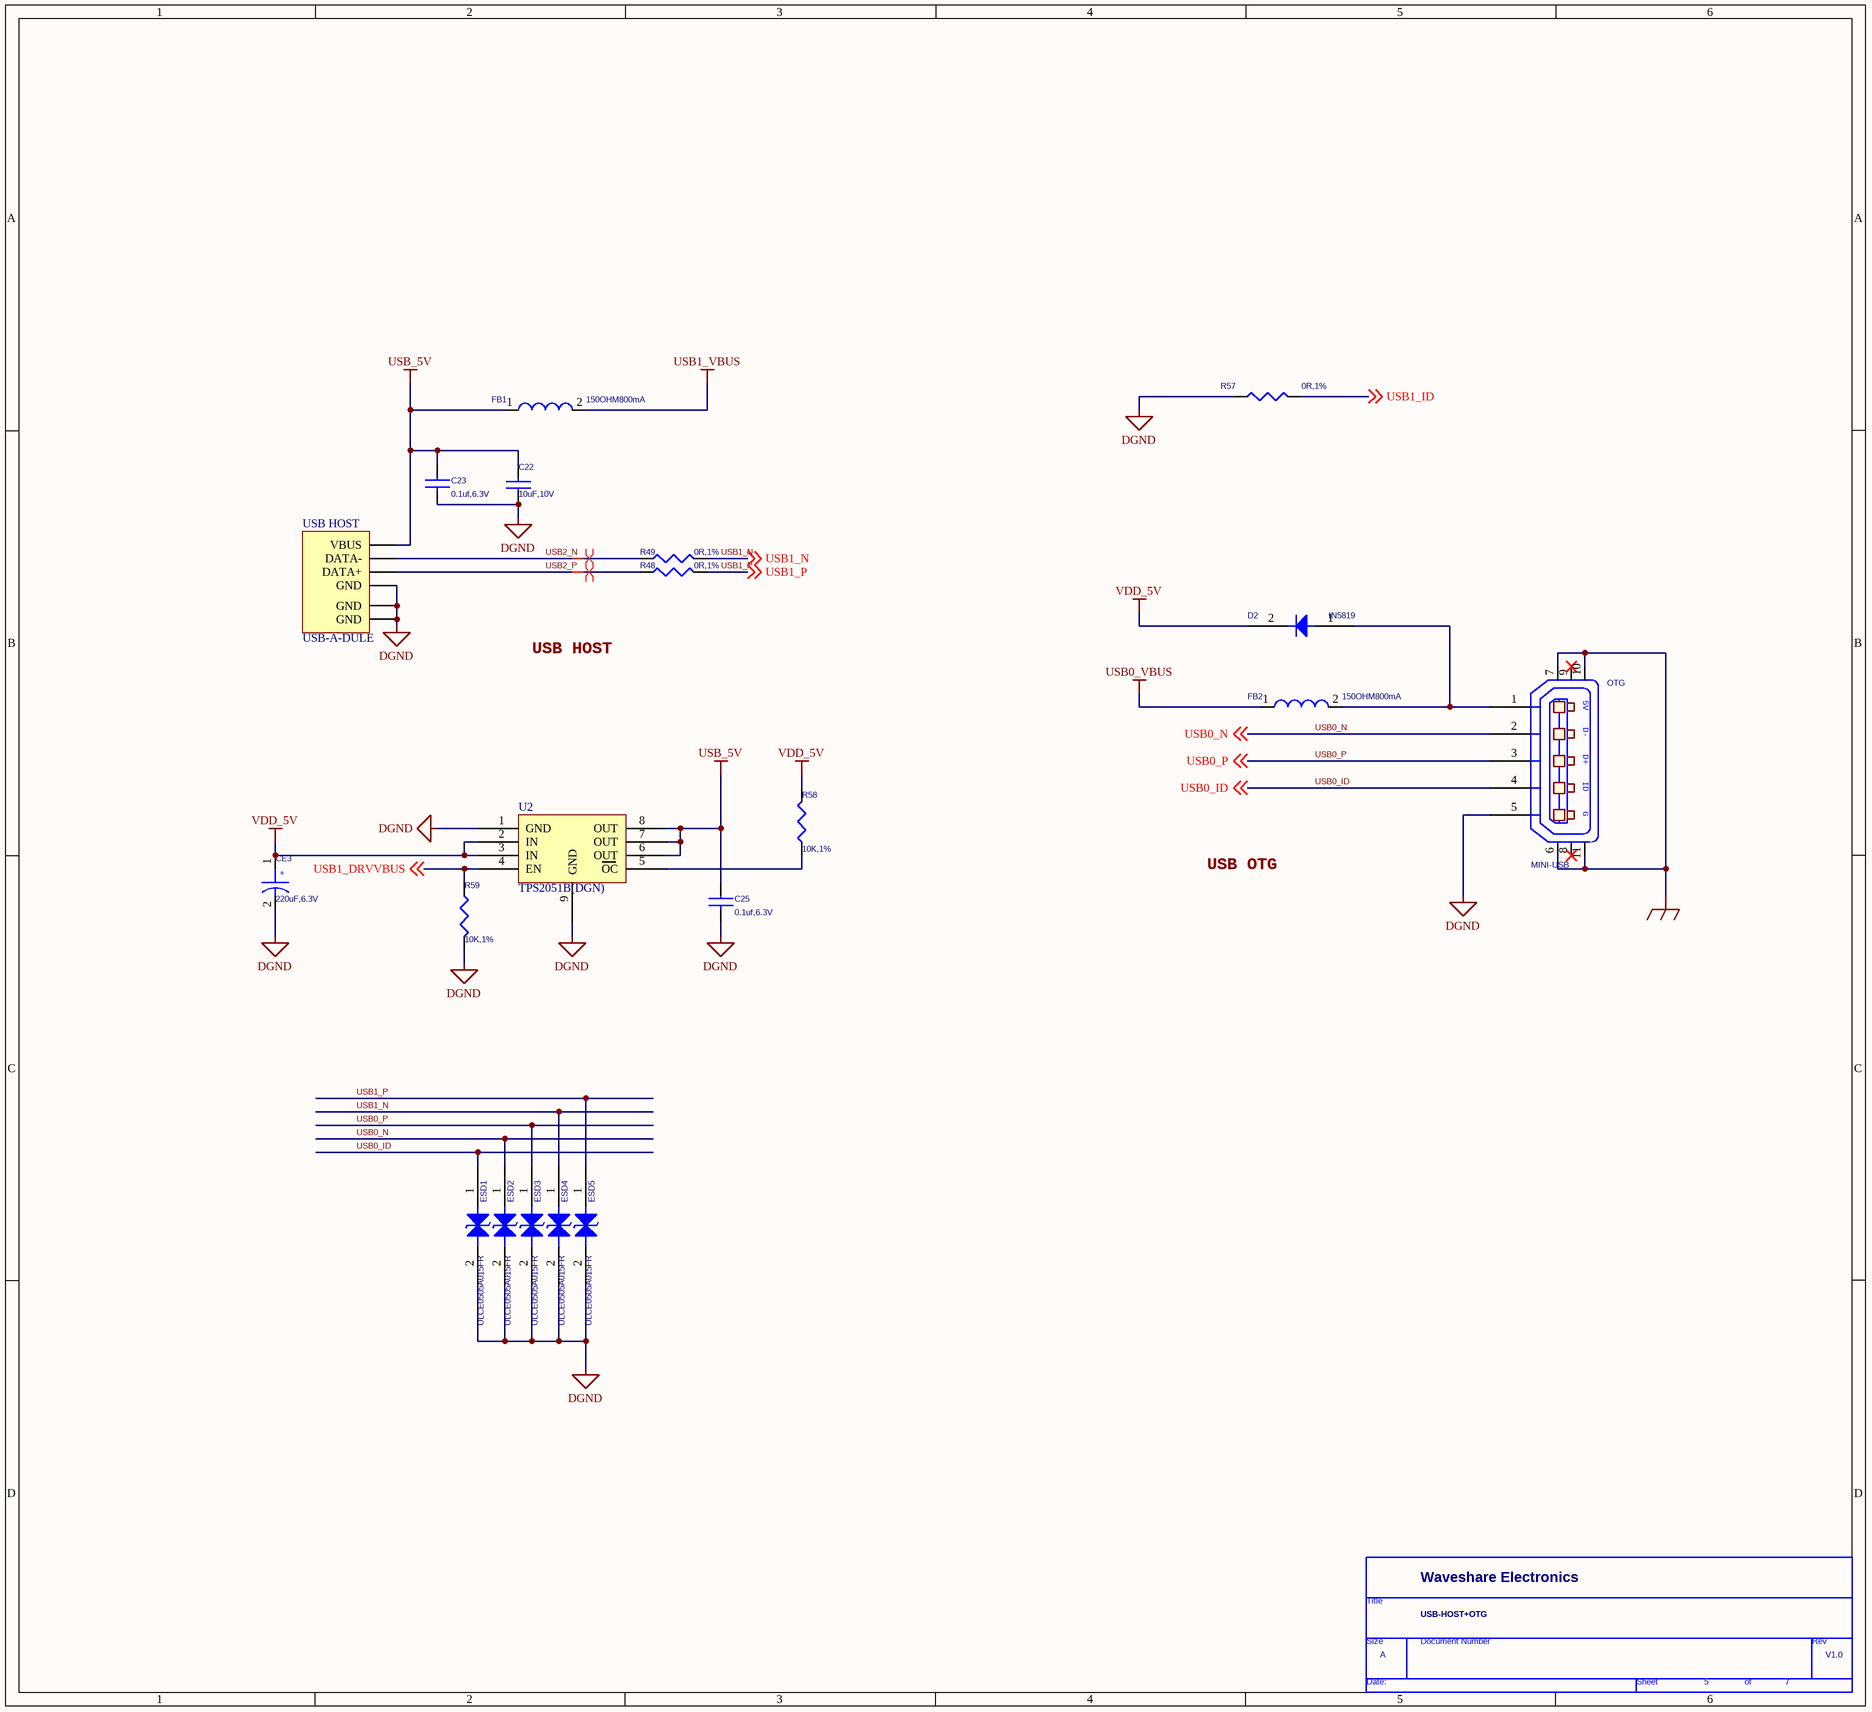
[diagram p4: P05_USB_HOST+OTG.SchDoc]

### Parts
(Parts that share a designator on the sheet are numbered #1, #2 ... from top to bottom, then left to right.)
*#5  Page Count: 7  Page Number: 5  Page Size: A  OrgName: Waveshare Electronics  Title: USB-HOST+OTG  RevCode: V1.0  (hidden comment: TitleBlock1)  (graphical)
C22  10uF,10V  [C0603]
C23  0.1uf,6.3V  [C0402]
C25  0.1uf,6.3V  [C0805]
CE3  220uF,6.3V  [C63_54]
D2  IN5819  [DO_214AC]
ESD1  ULCE0505A015FR  [R0402]
ESD2  ULCE0505A015FR  [R0402]
ESD3  ULCE0505A015FR  [R0402]
ESD4  ULCE0505A015FR  [R0402]
ESD5  ULCE0505A015FR  [R0402]
FB1  150OHM800mA  [L0805]
FB2  150OHM800mA  [L0805]
OTG  VAL: MINI-USB  [USB2]  (hidden comment: USB MICRO B Connector)
R48  0R,1%  [R0402]
R49  0R,1%  [R0402]
R57  0R,1%  [R0402]
R58  10K,1%  [R0402]
R59  10K,1%  [R0402]
U2  TPS2051B(DGN)  [MSOP-8]
USB_HOST  USB-A-DULE  [USB-2.0/F]

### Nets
DGND: C22.1 C23.2 C25.2 CE3.2 ESD1.2 ESD2.2 ESD3.2 ESD4.2 ESD5.2 OTG.5(P5) R57.1 R59.2 U2.1(GND) U2.9(GND) USB_HOST.4(GND) USB_HOST.5(GND) USB_HOST.6(GND)
GND_EARTH: OTG.6(SHLD1) OTG.7(SHLD2) OTG.10(SHLD5) OTG.11(SHLD6)
USB0_VBUS: FB2.1
USB1_VBUS: FB1.2
USB_5V: C22.2 C23.1 C25.1 FB1.1 U2.6(OUT) U2.7(OUT) U2.8(OUT) USB_HOST.1(VBUS)
VDD_5V: CE3.1 D2.2 R58.2 U2.2(IN) U2.3(IN)
USB0_ID: ESD1.1 OTG.4(P4) ; off-sheet USB0_ID
USB0_N: ESD2.1 OTG.2(P2) ; off-sheet USB0_N
USB0_P: ESD3.1 OTG.3(P3) ; off-sheet USB0_P
USB1_DRVVBUS: R59.1 U2.4(EN) ; off-sheet USB1_DRVVBUS
USB1_ID: R57.2 ; off-sheet USB1_ID
USB1_N: ESD4.1 R49.2 ; off-sheet USB1_N
USB1_P: ESD5.1 R48.2 ; off-sheet USB1_P
USB2_N: R49.1 USB_HOST.2(DATA-)
USB2_P: R48.1 USB_HOST.3(DATA+)
NetD2_1: D2.1 FB2.2 OTG.1(P1)
NetR58_1: R58.1 U2.5(OC)

Not connected (* = marked no-connect by the designer): OTG 8(SHLD3)* 9(SHLD4)*

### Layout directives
differential pair: USB2_N, USB2_P

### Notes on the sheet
- USB HOST
- USB OTG

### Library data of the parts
C22 = CAP_10uF_Y5V_10V_10%_0805: Desc: CAP CER 10UF 10V Y5V 0805
C23 C25 = CAP_0.1uF_X5R_6.3V_20% 0201: as C1 on sheet P03_SYSTEM
CE3 = CD6.3/2.5
FB1 FB2 = FER_180_200_0: Ferrite Bead 150 Ohm 800mA; Part Number: FER_180_200_0805; TIIntPartnumber: 1L0010; MfrNum: LI0805H151R-10; Mfr: Steward; Vendor: Digikey
OTG = USB MICRO B Connector: as DEBUG on sheet P04_DEBUG+TF
R48 R49 R57 = RES_4.75K_1/16W_1%_0402: RES 4.75K OHM 1/16W 1% 0402 SMD
R58 R59 = RES_100K_1/16W_1%_0402: Resistor 100Kohm 1/16W 1% 0402
USB_HOST = USB HOST

## Sheet P06_HDMI.SchDoc
size 379 x 260 mm
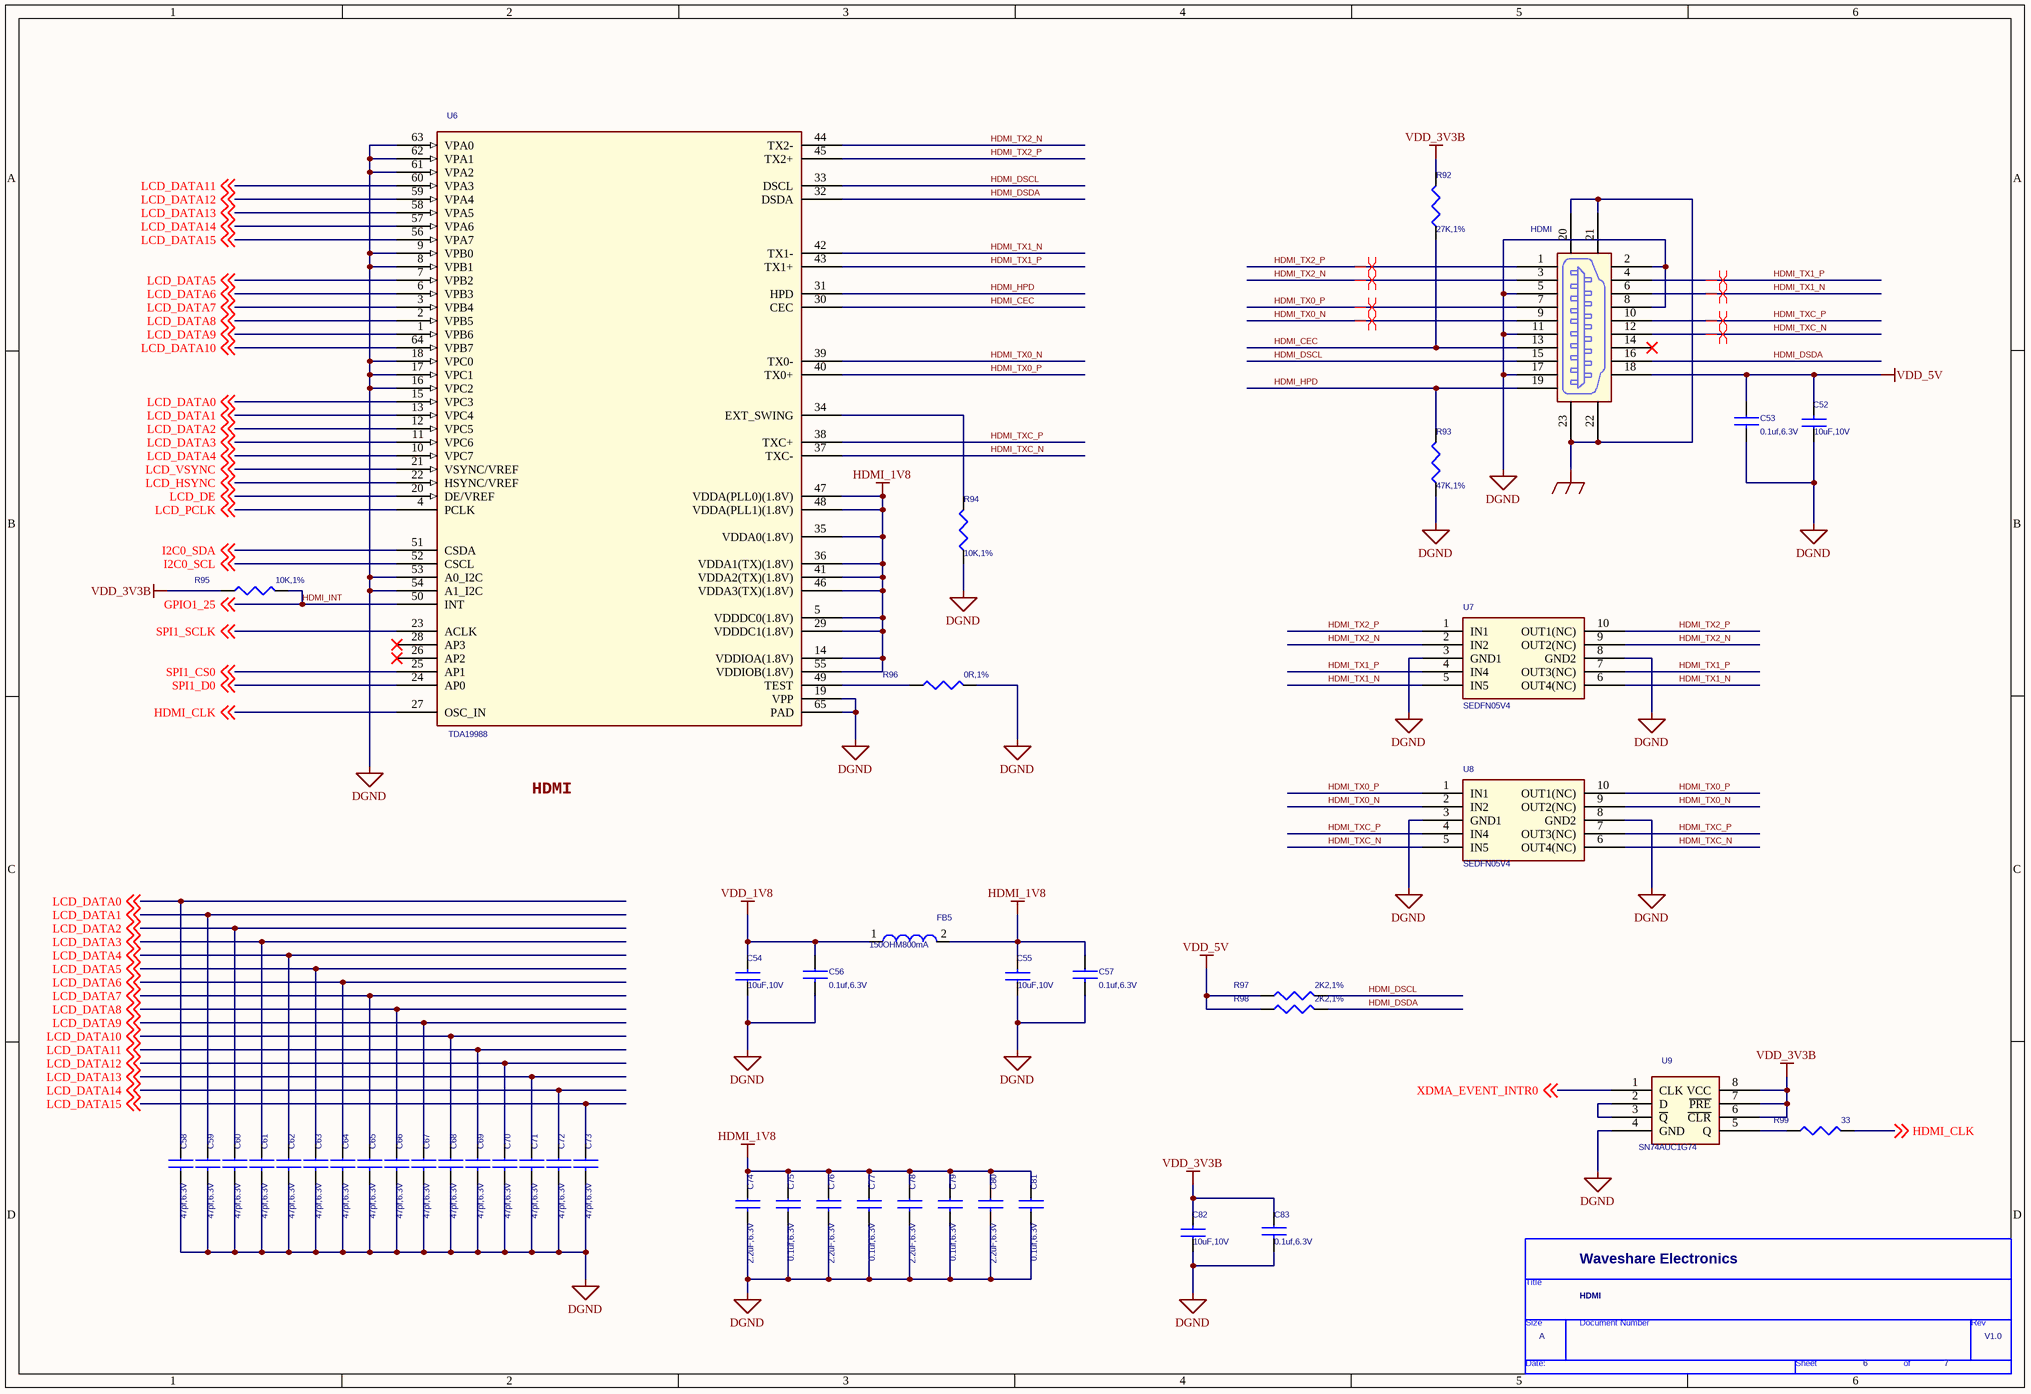
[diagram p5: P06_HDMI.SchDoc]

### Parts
(Parts that share a designator on the sheet are numbered #1, #2 ... from top to bottom, then left to right.)
*#6  Page Count: 7  Page Number: 6  Page Size: A  OrgName: Waveshare Electronics  Title: HDMI  RevCode: V1.0  (hidden comment: TitleBlock1)  (graphical)
C52  10uF,10V  [C0402]
C53  0.1uf,6.3V  [C0402]
C54  10uF,10V  [C0805]
C55  10uF,10V  [C0805]
C56  0.1uf,6.3V  [C0603]
C57  0.1uf,6.3V  [C0603]
C58  47pf,6.3V  [C0402]
C59  47pf,6.3V  [C0402]
C60  47pf,6.3V  [C0402]
C61  47pf,6.3V  [C0402]
C62  47pf,6.3V  [C0402]
C63  47pf,6.3V  [C0402]
C64  47pf,6.3V  [C0402]
C65  47pf,6.3V  [C0402]
C66  47pf,6.3V  [C0402]
C67  47pf,6.3V  [C0402]
C68  47pf,6.3V  [C0402]
C69  47pf,6.3V  [C0402]
C70  47pf,6.3V  [C0402]
C71  47pf,6.3V  [C0402]
C72  47pf,6.3V  [C0402]
C73  47pf,6.3V  [C0402]
C74  2.2uF,6.3V  [C0402]
C75  0.1uf,6.3V  [C0402]
C76  2.2uF,6.3V  [C0402]
C77  0.1uf,6.3V  [C0402]
C78  2.2uF,6.3V  [C0402]
C79  0.1uf,6.3V  [C0402]
C80  2.2uF,6.3V  [C0402]
C81  0.1uf,6.3V  [C0402]
C82  10uF,10V  [C0805]
C83  0.1uf,6.3V  [C0603]
FB5  150OHM800mA  [L0805]
HDMI  HDMI_A  [HDMI_A]  (value not drawn)
R92  27K,1%  [R0402]
R93  47K,1%  [R0402]
R94  10K,1%  [R0402]
R95  10K,1%  [R0402]
R96  0R,1%  [R0402]
R97  2K2,1%  [R0402]
R98  2K2,1%  [R0402]
R99  33  [R0402]
U6  TDA19988  [QFN64_9X9]
U7  SEDFN05V4  [SLP2510P8]
U8  SEDFN05V4  [SLP2510P8]
U9  SN74AUC1G74  [CFP50P630X90-8N]

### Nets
DGND: C52.1 C53.2 C54.1 C55.1 C56.2 C57.2 C58.2 C59.2 C60.2 C61.2 C62.2 C63.2 C64.2 C65.2 C66.2 C67.2 C68.2 C69.2 C70.2 C71.2 C72.2 C73.2 C74.2 C75.2 C76.2 C77.2 C78.2 C79.2 C80.2 C81.2 C82.1 C83.2 HDMI.2 HDMI.5 HDMI.8 HDMI.11 HDMI.17 R93.1 R94.1 R96.2 U6.8(VPB1) U6.9(VPB0) U6.16(VPC2) U6.17(VPC1) U6.18(VPC0) U6.19(VPP) U6.53(A0_I2C) U6.54(A1_I2C) U6.61(VPA2) U6.62(VPA1) U6.63(VPA0) U6.65(PAD) U7.3(GND1) U7.8(GND2) U8.3(GND1) U8.8(GND2) U9.4(GND)
GND_EARTH: HDMI.20 HDMI.21 HDMI.22 HDMI.23
HDMI_1V8: C55.2 C57.1 C74.1 C75.1 C76.1 C77.1 C78.1 C79.1 C80.1 C81.1 FB5.2 U6.5(VDDDC0(1.8V)) U6.14(VDDIOA(1.8V)) U6.29(VDDDC1(1.8V)) U6.35(VDDA0(1.8V)) U6.36(VDDA1(TX)(1.8V)) U6.41(VDDA2(TX)(1.8V)) U6.46(VDDA3(TX)(1.8V)) U6.47(VDDA(PLL0)(1.8V)) U6.48(VDDA(PLL1)(1.8V)) U6.55(VDDIOB(1.8V))
VDD_1V8: C54.2 C56.1 FB5.1
VDD_3V3B: C82.2 C83.1 R92.2 R95.1 U9.6(~{CLR}) U9.7(~{PRE}) U9.8(VCC)
VDD_5V: C52.2 C53.1 HDMI.18 R97.1 R98.1
HDMI_CEC: HDMI.13 R92.1 U6.30(CEC)
HDMI_CLK: R99.2 U6.27(OSC_IN) ; off-sheet HDMI_CLK
HDMI_DSCL: HDMI.15 R97.2 U6.33(DSCL)
HDMI_DSDA: HDMI.16 R98.2 U6.32(DSDA)
HDMI_HPD: HDMI.19 R93.2 U6.31(HPD)
HDMI_INT: R95.2 U6.50(INT) ; off-sheet GPIO1_25  [also labelled GPIO1_25]
HDMI_TX0_N: HDMI.9 U6.39(TX0-) U8.2(IN2) U8.9(OUT2(NC))
HDMI_TX0_P: HDMI.7 U6.40(TX0+) U8.1(IN1) U8.10(OUT1(NC))
HDMI_TX1_N: HDMI.6 U6.42(TX1-) U7.5(IN5) U7.6(OUT4(NC))
HDMI_TX1_P: HDMI.4 U6.43(TX1+) U7.4(IN4) U7.7(OUT3(NC))
HDMI_TX2_N: HDMI.3 U6.44(TX2-) U7.2(IN2) U7.9(OUT2(NC))
HDMI_TX2_P: HDMI.1($PIN0) U6.45(TX2+) U7.1(IN1) U7.10(OUT1(NC))
HDMI_TXC_N: HDMI.12 U6.37(TXC-) U8.5(IN5) U8.6(OUT4(NC))
HDMI_TXC_P: HDMI.10 U6.38(TXC+) U8.4(IN4) U8.7(OUT3(NC))
I2C0_SCL: U6.52(CSCL) ; off-sheet I2C0_SCL
I2C0_SDA: U6.51(CSDA) ; off-sheet I2C0_SDA
LCD_DATA0: C58.1 U6.15(VPC3) ; off-sheet LCD_DATA0
LCD_DATA1: C59.1 U6.13(VPC4) ; off-sheet LCD_DATA1
LCD_DATA2: C60.1 U6.12(VPC5) ; off-sheet LCD_DATA2
LCD_DATA3: C61.1 U6.11(VPC6) ; off-sheet LCD_DATA3
LCD_DATA4: C62.1 U6.10(VPC7) ; off-sheet LCD_DATA4
LCD_DATA5: C63.1 U6.7(VPB2) ; off-sheet LCD_DATA5
LCD_DATA6: C64.1 U6.6(VPB3) ; off-sheet LCD_DATA6
LCD_DATA7: C65.1 U6.3(VPB4) ; off-sheet LCD_DATA7
LCD_DATA8: C66.1 U6.2(VPB5) ; off-sheet LCD_DATA8
LCD_DATA9: C67.1 U6.1(VPB6) ; off-sheet LCD_DATA9
LCD_DATA10: C68.1 U6.64(VPB7) ; off-sheet LCD_DATA10
LCD_DATA11: C69.1 U6.60(VPA3) ; off-sheet LCD_DATA11
LCD_DATA12: C70.1 U6.59(VPA4) ; off-sheet LCD_DATA12
LCD_DATA13: C71.1 U6.58(VPA5) ; off-sheet LCD_DATA13
LCD_DATA14: C72.1 U6.57(VPA6) ; off-sheet LCD_DATA14
LCD_DATA15: C73.1 U6.56(VPA7) ; off-sheet LCD_DATA15
LCD_DE: U6.20(DE/VREF) ; off-sheet LCD_DE
LCD_HSYNC: U6.22(HSYNC/VREF) ; off-sheet LCD_HSYNC
LCD_PCLK: U6.4(PCLK) ; off-sheet LCD_PCLK
LCD_VSYNC: U6.21(VSYNC/VREF) ; off-sheet LCD_VSYNC
SPI1_CS0: U6.25(AP1) ; off-sheet SPI1_CS0
SPI1_D0: U6.24(AP0) ; off-sheet SPI1_D0
SPI1_SCLK: U6.23(ACLK) ; off-sheet SPI1_SCLK
XDMA_EVENT_INTR0: U9.1(CLK) ; off-sheet XDMA_EVENT_INTR0
NetR94_2: R94.2 U6.34(EXT_SWING)
NetR96_1: R96.1 U6.49(TEST)
NetR99_1: R99.1 U9.5(Q)
NetU9_2: U9.2(D) U9.3(~{Q})

Not connected (* = marked no-connect by the designer): HDMI 14*; U6 26(AP2)* 28(AP3)*

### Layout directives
differential pair: HDMI_TX0_N, HDMI_TX0_P, HDMI_TX1_N, HDMI_TX1_P, HDMI_TX2_N, HDMI_TX2_P, HDMI_TXC_N, HDMI_TXC_P

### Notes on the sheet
- HDMI

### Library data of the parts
C52 C54 C55 C82 = CAP_10uF_Y5V_10V_10%_0805: Desc: CAP CER 10UF 10V Y5V 0805
C53 C56-C73 C75 C77 C79 C81 C83 = CAP_0.1uF_X5R_6.3V_20% 0201: as C1 on sheet P03_SYSTEM
C74 C76 C78 C80 = CAP_2.2uF_X5R_6.3V_10%_0402: Desc: CAP, CER, X7R, 0402, 50V, 10%, 0.1uF
FB5 = FER_180_200_0805: Ferrite Bead 150 Ohm 800mA; Mfr: Steward; MfrNum: LI0805H151R-10; TIIntPartnumber: 1L0010; Vendor: Digikey
R92-R96 = RES_10K_1/16W_1%_0402: Resistor 10Kohm 1/16W 1% 0402
R97 R98 = RES_1.5K_1/16W_5%_0402: RES 1.5K OHM 1/16W 5% 0402 SMD
R99 = RES_33_0402: Part Number: RES_33_0201
U9 = IC_SN74AUC1G74

## Sheet P07_EXT-INTERFACE.SchDoc
size 386 x 246 mm
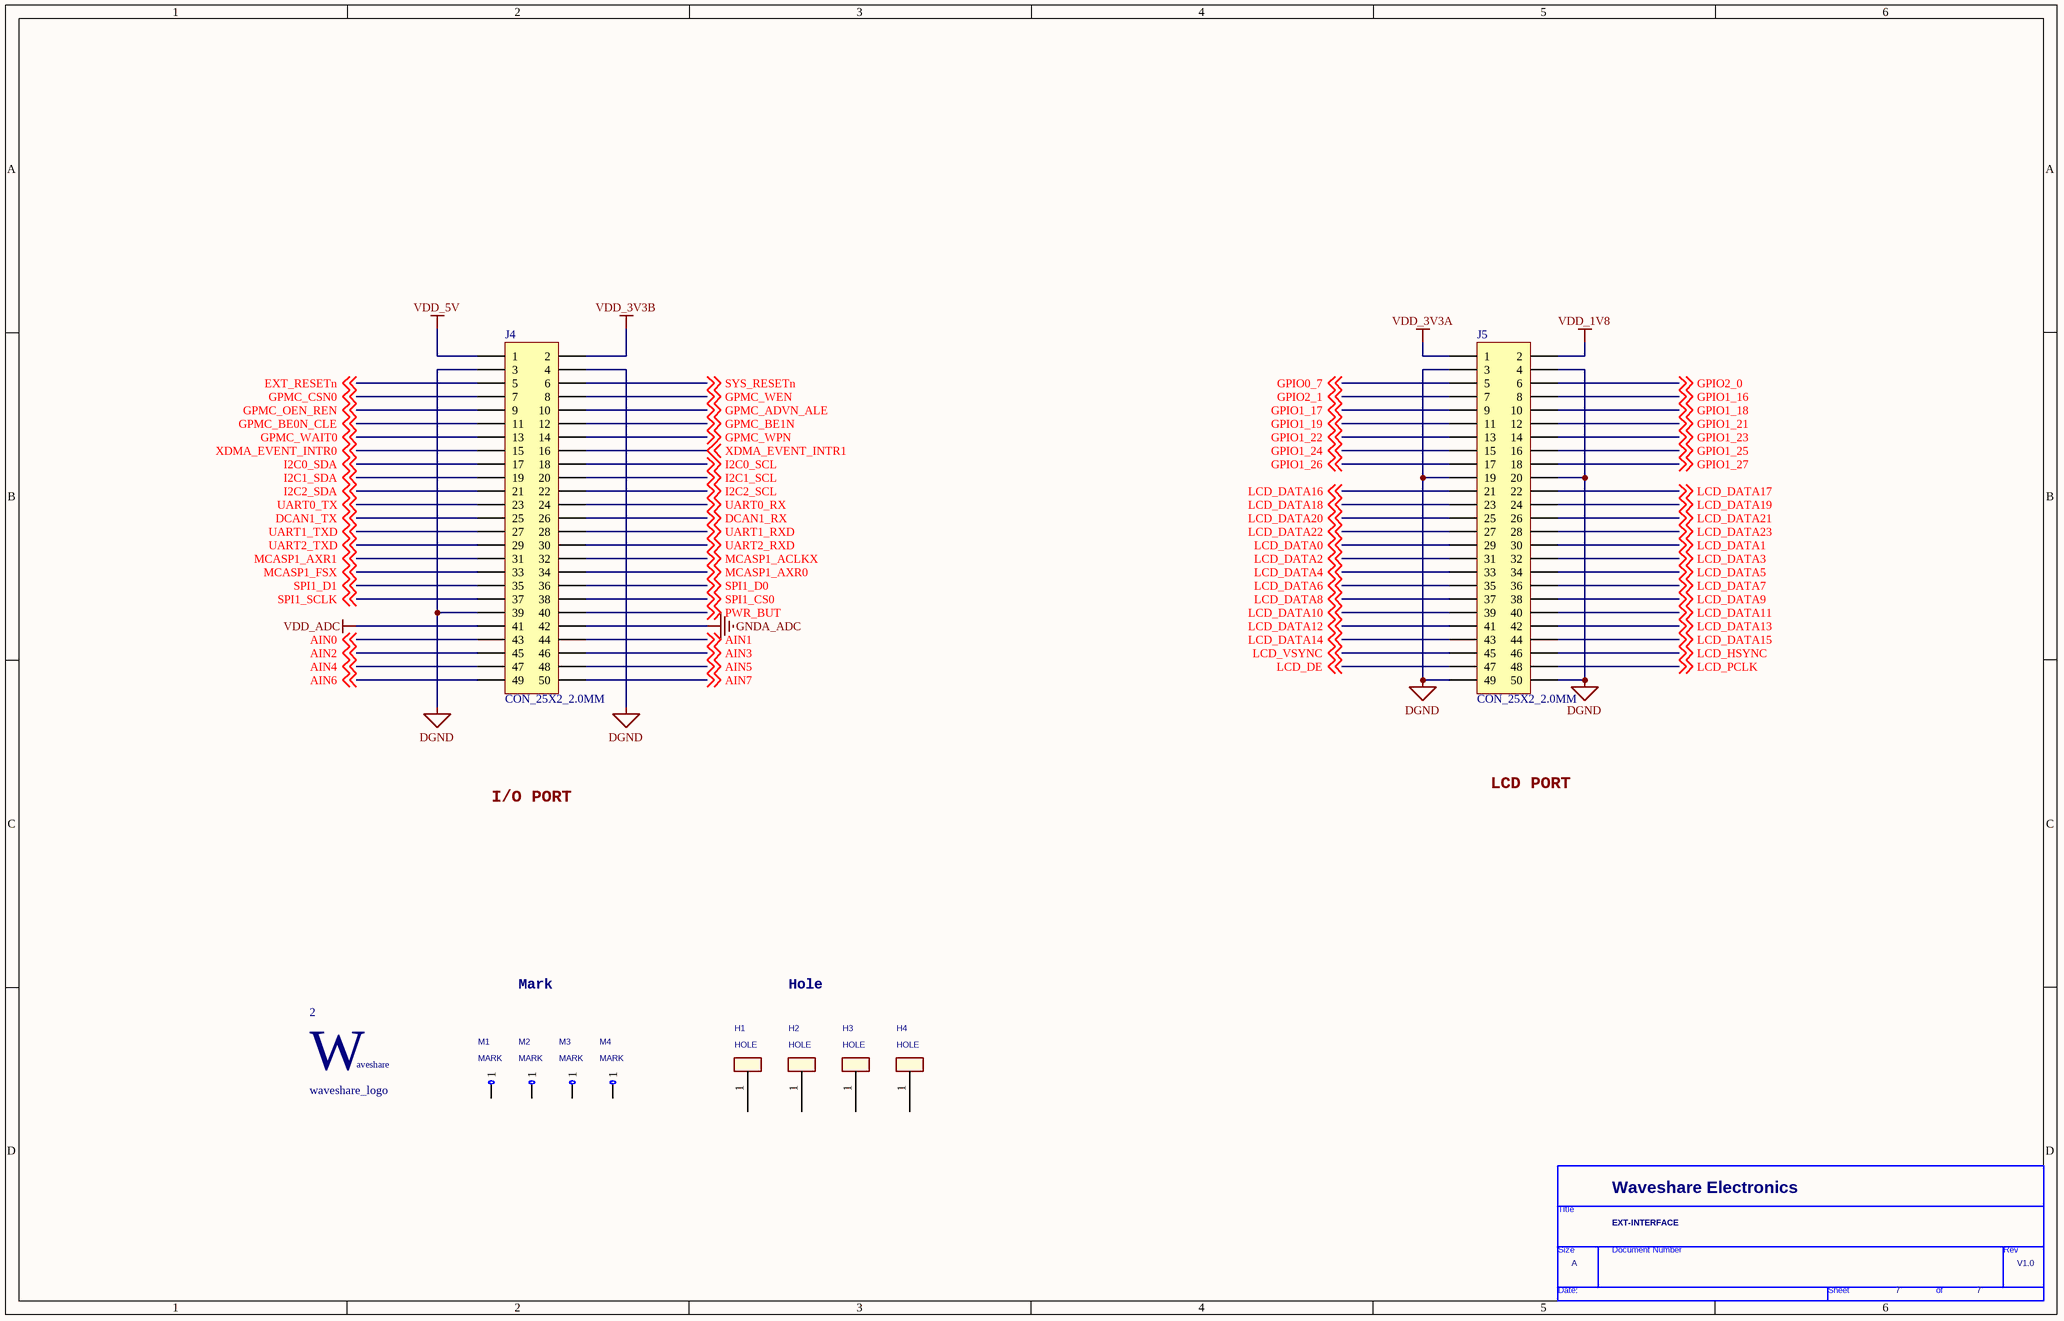
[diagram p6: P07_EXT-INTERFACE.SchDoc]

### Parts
(Parts that share a designator on the sheet are numbered #1, #2 ... from top to bottom, then left to right.)
2  waveshare_logo  [WS_symbol_XXL]
*#7  Page Count: 7  Page Size: A  OrgName: Waveshare Electronics  Title: EXT-INTERFACE  RevCode: V1.0  (hidden comment: TitleBlock1)  (graphical)
H1  HOLE  [PAD_M3]
H2  HOLE  [PAD_M3]
H3  HOLE  [PAD_M3]
H4  HOLE  [PAD_M3]
J4  CON_25X2_2.0MM  [Header 25X2 - 2mm]
J5  CON_25X2_2.0MM  [Header 25X2 - 2mm]
M1  MARK  [MARK]
M2  MARK  [MARK]
M3  MARK  [MARK]
M4  MARK  [MARK]

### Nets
DGND: J4.3 J4.4 J4.39 J5.3 J5.4 J5.19 J5.20 J5.49 J5.50
GNDA_ADC: J4.42
VDD_1V8: J5.2
VDD_3V3A: J5.1
VDD_3V3B: J4.2
VDD_5V: J4.1
VDD_ADC: J4.41
AIN0: J4.43 ; off-sheet AIN0
AIN1: J4.44 ; off-sheet AIN1
AIN2: J4.45 ; off-sheet AIN2
AIN3: J4.46 ; off-sheet AIN3
AIN4: J4.47 ; off-sheet AIN4
AIN5: J4.48 ; off-sheet AIN5
AIN6: J4.49 ; off-sheet AIN6
AIN7: J4.50 ; off-sheet AIN7
DCAN1_RX: J4.26 ; off-sheet DCAN1_RX
DCAN1_TX: J4.25 ; off-sheet DCAN1_TX
EXT_RESETn: J4.5 ; off-sheet EXT_RESETn
GPIO0_7: J5.5 ; off-sheet GPIO0_7
GPIO1_16: J5.8 ; off-sheet GPIO1_16
GPIO1_17: J5.9 ; off-sheet GPIO1_17
GPIO1_18: J5.10 ; off-sheet GPIO1_18
GPIO1_19: J5.11 ; off-sheet GPIO1_19
GPIO1_21: J5.12 ; off-sheet GPIO1_21
GPIO1_22: J5.13 ; off-sheet GPIO1_22
GPIO1_23: J5.14 ; off-sheet GPIO1_23
GPIO1_24: J5.15 ; off-sheet GPIO1_24
GPIO1_25: J5.16 ; off-sheet GPIO1_25  [project net HDMI_INT]
GPIO1_26: J5.17 ; off-sheet GPIO1_26
GPIO1_27: J5.18 ; off-sheet GPIO1_27
GPIO2_0: J5.6 ; off-sheet GPIO2_0
GPIO2_1: J5.7 ; off-sheet GPIO2_1
GPMC_ADVN_ALE: J4.10 ; off-sheet GPMC_ADVN_ALE
GPMC_BE0N_CLE: J4.11 ; off-sheet GPMC_BE0N_CLE
GPMC_BE1N: J4.12 ; off-sheet GPMC_BE1N
GPMC_CSN0: J4.7 ; off-sheet GPMC_CSN0
GPMC_OEN_REN: J4.9 ; off-sheet GPMC_OEN_REN
GPMC_WAIT0: J4.13 ; off-sheet GPMC_WAIT0
GPMC_WEN: J4.8 ; off-sheet GPMC_WEN
GPMC_WPN: J4.14 ; off-sheet GPMC_WPN
I2C0_SCL: J4.18 ; off-sheet I2C0_SCL
I2C0_SDA: J4.17 ; off-sheet I2C0_SDA
I2C1_SCL: J4.20 ; off-sheet I2C1_SCL
I2C1_SDA: J4.19 ; off-sheet I2C1_SDA
I2C2_SCL: J4.22 ; off-sheet I2C2_SCL
I2C2_SDA: J4.21 ; off-sheet I2C2_SDA
LCD_DATA0: J5.29 ; off-sheet LCD_DATA0
LCD_DATA1: J5.30 ; off-sheet LCD_DATA1
LCD_DATA2: J5.31 ; off-sheet LCD_DATA2
LCD_DATA3: J5.32 ; off-sheet LCD_DATA3
LCD_DATA4: J5.33 ; off-sheet LCD_DATA4
LCD_DATA5: J5.34 ; off-sheet LCD_DATA5
LCD_DATA6: J5.35 ; off-sheet LCD_DATA6
LCD_DATA7: J5.36 ; off-sheet LCD_DATA7
LCD_DATA8: J5.37 ; off-sheet LCD_DATA8
LCD_DATA9: J5.38 ; off-sheet LCD_DATA9
LCD_DATA10: J5.39 ; off-sheet LCD_DATA10
LCD_DATA11: J5.40 ; off-sheet LCD_DATA11
LCD_DATA12: J5.41 ; off-sheet LCD_DATA12
LCD_DATA13: J5.42 ; off-sheet LCD_DATA13
LCD_DATA14: J5.43 ; off-sheet LCD_DATA14
LCD_DATA15: J5.44 ; off-sheet LCD_DATA15
LCD_DATA16: J5.21 ; off-sheet LCD_DATA16
LCD_DATA17: J5.22 ; off-sheet LCD_DATA17
LCD_DATA18: J5.23 ; off-sheet LCD_DATA18
LCD_DATA19: J5.24 ; off-sheet LCD_DATA19
LCD_DATA20: J5.25 ; off-sheet LCD_DATA20
LCD_DATA21: J5.26 ; off-sheet LCD_DATA21
LCD_DATA22: J5.27 ; off-sheet LCD_DATA22
LCD_DATA23: J5.28 ; off-sheet LCD_DATA23
LCD_DE: J5.47 ; off-sheet LCD_DE
LCD_HSYNC: J5.46 ; off-sheet LCD_HSYNC
LCD_PCLK: J5.48 ; off-sheet LCD_PCLK
LCD_VSYNC: J5.45 ; off-sheet LCD_VSYNC
MCASP1_ACLKX: J4.32 ; off-sheet MCASP1_ACLKX
MCASP1_AXR0: J4.34 ; off-sheet MCASP1_AXR0
MCASP1_AXR1: J4.31 ; off-sheet MCASP1_AXR1
MCASP1_FSX: J4.33 ; off-sheet MCASP1_FSX
PWR_BUT: J4.40 ; off-sheet PWR_BUT
SPI1_CS0: J4.38 ; off-sheet SPI1_CS0
SPI1_D0: J4.36 ; off-sheet SPI1_D0
SPI1_D1: J4.35 ; off-sheet SPI1_D1
SPI1_SCLK: J4.37 ; off-sheet SPI1_SCLK
SYS_RESETn: J4.6 ; off-sheet SYS_RESETn
UART0_RX: J4.24 ; off-sheet UART0_RX
UART0_TX: J4.23 ; off-sheet UART0_TX
UART1_RXD: J4.28 ; off-sheet UART1_RXD
UART1_TXD: J4.27 ; off-sheet UART1_TXD
UART2_RXD: J4.30 ; off-sheet UART2_RXD
UART2_TXD: J4.29 ; off-sheet UART2_TXD
XDMA_EVENT_INTR0: J4.15 ; off-sheet XDMA_EVENT_INTR0
XDMA_EVENT_INTR1: J4.16 ; off-sheet XDMA_EVENT_INTR1

Not connected (* = marked no-connect by the designer): H1 1; H2 1; H3 1; H4 1; M1 1; M2 1; M3 1; M4 1

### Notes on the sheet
- I/O PORT
- LCD PORT
- Mark
- Hole

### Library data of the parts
H1-H4 = TEST POINT
J4 J5 = Header 25X2: Header, 25-Pin, Dual row
M1-M4 = TEST

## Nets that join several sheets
DGND: P02_CM-INTERFACE (49 pins), P03_SYSTEM (32 pins), P04_DEBUG+TF (20 pins), P05_USB_HOST+OTG (17 pins), P06_HDMI (57 pins), P07_EXT-INTERFACE (9 pins)
GND_EARTH: P04_DEBUG+TF (13 pins), P05_USB_HOST+OTG (OTG.6 OTG.7 OTG.10 OTG.11), P06_HDMI (HDMI.20 HDMI.21 HDMI.22 HDMI.23)
GNDA_ADC: P02_CM-INTERFACE (J1.88), P07_EXT-INTERFACE (J4.42)
USB0_VBUS: P02_CM-INTERFACE (J2.29), P05_USB_HOST+OTG (FB2.1)
USB1_VBUS: P02_CM-INTERFACE (J2.39), P05_USB_HOST+OTG (FB1.2)
VCC3V3_BAT: P02_CM-INTERFACE (J1.1 J1.3), P03_SYSTEM (C3.1 C4.2 R44.1)
VDD_1V8: P02_CM-INTERFACE (J1.7 J1.9), P06_HDMI (C54.2 C56.1 FB5.1), P07_EXT-INTERFACE (J5.2)
VDD_3V3A: P02_CM-INTERFACE (J2.2 J2.4), P07_EXT-INTERFACE (J5.1)
VDD_3V3B: P02_CM-INTERFACE (J2.1 J2.3), P03_SYSTEM (20 pins), P04_DEBUG+TF (14 pins), P06_HDMI (7 pins), P07_EXT-INTERFACE (J4.2)
VDD_5V: P02_CM-INTERFACE (J1.2 J1.4), P03_SYSTEM (7 pins), P05_USB_HOST+OTG (5 pins), P06_HDMI (5 pins), P07_EXT-INTERFACE (J4.1)
VDD_ADC: P02_CM-INTERFACE (J1.86), P07_EXT-INTERFACE (J4.41)
VDD_ETH: P02_CM-INTERFACE (J1.8 J1.10), P04_DEBUG+TF (R50.1)
AIN0: P02_CM-INTERFACE (J1.92), P07_EXT-INTERFACE (J4.43)
AIN1: P02_CM-INTERFACE (J1.91), P07_EXT-INTERFACE (J4.44)
AIN2: P02_CM-INTERFACE (J1.94), P07_EXT-INTERFACE (J4.45)
AIN3: P02_CM-INTERFACE (J1.93), P07_EXT-INTERFACE (J4.46)
AIN4: P02_CM-INTERFACE (J1.96), P07_EXT-INTERFACE (J4.47)
AIN5: P02_CM-INTERFACE (J1.95), P07_EXT-INTERFACE (J4.48)
AIN6: P02_CM-INTERFACE (J1.98), P07_EXT-INTERFACE (J4.49)
AIN7: P02_CM-INTERFACE (J1.97), P07_EXT-INTERFACE (J4.50)
DCAN1_RX: P02_CM-INTERFACE (J1.45), P07_EXT-INTERFACE (J4.26)
DCAN1_TX: P02_CM-INTERFACE (J1.46), P07_EXT-INTERFACE (J4.25)
EXT_RESETn: P02_CM-INTERFACE (J1.75), P03_SYSTEM (RESET.1), P07_EXT-INTERFACE (J4.5)
GPIO0_7: P02_CM-INTERFACE (J2.50), P07_EXT-INTERFACE (J5.5)
GPIO1_16: P02_CM-INTERFACE (J2.51), P03_SYSTEM (R18.1), P07_EXT-INTERFACE (J5.8)
GPIO1_17: P02_CM-INTERFACE (J2.54), P03_SYSTEM (R22.1), P07_EXT-INTERFACE (J5.9)
GPIO1_18: P02_CM-INTERFACE (J2.53), P07_EXT-INTERFACE (J5.10)
GPIO1_19: P02_CM-INTERFACE (J2.56), P07_EXT-INTERFACE (J5.11)
GPIO1_21: P02_CM-INTERFACE (J2.55), P07_EXT-INTERFACE (J5.12)
GPIO1_22: P02_CM-INTERFACE (J2.58), P07_EXT-INTERFACE (J5.13)
GPIO1_23: P02_CM-INTERFACE (J2.57), P07_EXT-INTERFACE (J5.14)
GPIO1_24: P02_CM-INTERFACE (J2.60), P07_EXT-INTERFACE (J5.15)
GPIO1_26: P02_CM-INTERFACE (J2.62), P07_EXT-INTERFACE (J5.17)
GPIO1_27: P02_CM-INTERFACE (J2.61), P07_EXT-INTERFACE (J5.18)
GPIO2_0: P02_CM-INTERFACE (J2.49), P07_EXT-INTERFACE (J5.6)
GPIO2_1: P02_CM-INTERFACE (J2.52), P07_EXT-INTERFACE (J5.7)
GPMC_ADVN_ALE: P02_CM-INTERFACE (J2.21), P07_EXT-INTERFACE (J4.10)
GPMC_BE0N_CLE: P02_CM-INTERFACE (J2.26), P07_EXT-INTERFACE (J4.11)
GPMC_BE1N: P02_CM-INTERFACE (J2.23), P07_EXT-INTERFACE (J4.12)
GPMC_CSN0: P02_CM-INTERFACE (J2.22), P07_EXT-INTERFACE (J4.7)
GPMC_OEN_REN: P02_CM-INTERFACE (J2.24), P07_EXT-INTERFACE (J4.9)
GPMC_WAIT0: P02_CM-INTERFACE (J2.28), P07_EXT-INTERFACE (J4.13)
GPMC_WEN: P02_CM-INTERFACE (J2.19), P07_EXT-INTERFACE (J4.8)
GPMC_WPN: P02_CM-INTERFACE (J2.25), P07_EXT-INTERFACE (J4.14)
GR_N: P02_CM-INTERFACE (J1.19), P04_DEBUG+TF (ETHERNET.10)
GR_P: P02_CM-INTERFACE (J1.21), P04_DEBUG+TF (ETHERNET.9)
HDMI_INT: P02_CM-INTERFACE (J2.59), P06_HDMI (R95.2 U6.50), P07_EXT-INTERFACE (J5.16)
I2C0_SCL: P02_CM-INTERFACE (J1.35), P06_HDMI (U6.52), P07_EXT-INTERFACE (J4.18)
I2C0_SDA: P02_CM-INTERFACE (J1.36), P06_HDMI (U6.51), P07_EXT-INTERFACE (J4.17)
I2C1_SCL: P02_CM-INTERFACE (J1.37), P07_EXT-INTERFACE (J4.20)
I2C1_SDA: P02_CM-INTERFACE (J1.38), P07_EXT-INTERFACE (J4.19)
I2C2_SCL: P02_CM-INTERFACE (J1.39), P07_EXT-INTERFACE (J4.22)
I2C2_SDA: P02_CM-INTERFACE (J1.40), P07_EXT-INTERFACE (J4.21)
JTAG_EMU0: P02_CM-INTERFACE (J1.63), P04_DEBUG+TF (JTAG.13 R72.2)
JTAG_EMU1: P02_CM-INTERFACE (J1.65), P04_DEBUG+TF (JTAG.14 R73.2)
JTAG_TCK: P02_CM-INTERFACE (J1.61), P04_DEBUG+TF (JTAG.9 JTAG.11)
JTAG_TDI: P02_CM-INTERFACE (J1.62), P04_DEBUG+TF (JTAG.3)
JTAG_TDO: P02_CM-INTERFACE (J1.64), P04_DEBUG+TF (JTAG.7)
JTAG_TMS: P02_CM-INTERFACE (J1.59), P04_DEBUG+TF (JTAG.1)
JTAG_TRSTn: P02_CM-INTERFACE (J1.60), P04_DEBUG+TF (JTAG.2 R74.2)
LCD_DATA0: P02_CM-INTERFACE (J2.76), P03_SYSTEM (R16.2 R40.1), P06_HDMI (C58.1 U6.15), P07_EXT-INTERFACE (J5.29)
LCD_DATA1: P02_CM-INTERFACE (J2.75), P03_SYSTEM (R15.2 R39.1), P06_HDMI (C59.1 U6.13), P07_EXT-INTERFACE (J5.30)
LCD_DATA2: P02_CM-INTERFACE (J2.78), P03_SYSTEM (BOOT.1 R14.2), P06_HDMI (C60.1 U6.12), P07_EXT-INTERFACE (J5.31)
LCD_DATA3: P02_CM-INTERFACE (J2.77), P03_SYSTEM (R13.2 R37.1), P06_HDMI (C61.1 U6.11), P07_EXT-INTERFACE (J5.32)
LCD_DATA4: P02_CM-INTERFACE (J2.80), P03_SYSTEM (R12.2 R36.1), P06_HDMI (C62.1 U6.10), P07_EXT-INTERFACE (J5.33)
LCD_DATA5: P02_CM-INTERFACE (J2.79), P03_SYSTEM (R11.2 R35.1), P06_HDMI (C63.1 U6.7), P07_EXT-INTERFACE (J5.34)
LCD_DATA6: P02_CM-INTERFACE (J2.82), P03_SYSTEM (R10.2 R34.1), P06_HDMI (C64.1 U6.6), P07_EXT-INTERFACE (J5.35)
LCD_DATA7: P02_CM-INTERFACE (J2.81), P03_SYSTEM (R9.2 R33.1), P06_HDMI (C65.1 U6.3), P07_EXT-INTERFACE (J5.36)
LCD_DATA8: P02_CM-INTERFACE (J2.86), P03_SYSTEM (R8.2 R32.1), P06_HDMI (C66.1 U6.2), P07_EXT-INTERFACE (J5.37)
LCD_DATA9: P02_CM-INTERFACE (J2.85), P03_SYSTEM (R7.2 R31.1), P06_HDMI (C67.1 U6.1), P07_EXT-INTERFACE (J5.38)
LCD_DATA10: P02_CM-INTERFACE (J2.88), P03_SYSTEM (R6.2 R30.1), P06_HDMI (C68.1 U6.64), P07_EXT-INTERFACE (J5.39)
LCD_DATA11: P02_CM-INTERFACE (J2.87), P03_SYSTEM (R5.2 R29.1), P06_HDMI (C69.1 U6.60), P07_EXT-INTERFACE (J5.40)
LCD_DATA12: P02_CM-INTERFACE (J2.90), P03_SYSTEM (R4.2 R28.1), P06_HDMI (C70.1 U6.59), P07_EXT-INTERFACE (J5.41)
LCD_DATA13: P02_CM-INTERFACE (J2.89), P03_SYSTEM (R3.2 R27.1), P06_HDMI (C71.1 U6.58), P07_EXT-INTERFACE (J5.42)
LCD_DATA14: P02_CM-INTERFACE (J2.92), P03_SYSTEM (R2.2 R26.1), P06_HDMI (C72.1 U6.57), P07_EXT-INTERFACE (J5.43)
LCD_DATA15: P02_CM-INTERFACE (J2.91), P03_SYSTEM (R1.2 R25.1), P06_HDMI (C73.1 U6.56), P07_EXT-INTERFACE (J5.44)
LCD_DATA16: P02_CM-INTERFACE (J2.66), P07_EXT-INTERFACE (J5.21)
LCD_DATA17: P02_CM-INTERFACE (J2.65), P07_EXT-INTERFACE (J5.22)
LCD_DATA18: P02_CM-INTERFACE (J2.68), P07_EXT-INTERFACE (J5.23)
LCD_DATA19: P02_CM-INTERFACE (J2.67), P07_EXT-INTERFACE (J5.24)
LCD_DATA20: P02_CM-INTERFACE (J2.70), P07_EXT-INTERFACE (J5.25)
LCD_DATA21: P02_CM-INTERFACE (J2.69), P07_EXT-INTERFACE (J5.26)
LCD_DATA22: P02_CM-INTERFACE (J2.72), P07_EXT-INTERFACE (J5.27)
LCD_DATA23: P02_CM-INTERFACE (J2.71), P07_EXT-INTERFACE (J5.28)
LCD_DE: P02_CM-INTERFACE (J2.98), P06_HDMI (U6.20), P07_EXT-INTERFACE (J5.47)
LCD_HSYNC: P02_CM-INTERFACE (J2.95), P06_HDMI (U6.22), P07_EXT-INTERFACE (J5.46)
LCD_PCLK: P02_CM-INTERFACE (J2.97), P06_HDMI (U6.4), P07_EXT-INTERFACE (J5.48)
LCD_VSYNC: P02_CM-INTERFACE (J2.96), P06_HDMI (U6.21), P07_EXT-INTERFACE (J5.45)
MCASP1_ACLKX: P02_CM-INTERFACE (J1.69), P07_EXT-INTERFACE (J4.32)
MCASP1_AXR0: P02_CM-INTERFACE (J1.71), P07_EXT-INTERFACE (J4.34)
MCASP1_AXR1: P02_CM-INTERFACE (J1.68), P07_EXT-INTERFACE (J4.31)
MCASP1_FSX: P02_CM-INTERFACE (J1.70), P07_EXT-INTERFACE (J4.33)
MMC0_CD: P02_CM-INTERFACE (J1.30), P04_DEBUG+TF (R71.2 TF_Card.9)
MMC0_CLKO: P02_CM-INTERFACE (J1.32), P04_DEBUG+TF (R68.2 TF_Card.5)
MMC0_CMD: P02_CM-INTERFACE (J1.31), P04_DEBUG+TF (R67.2 TF_Card.3)
MMC0_DAT0: P02_CM-INTERFACE (J1.26), P04_DEBUG+TF (R69.2 TF_Card.7)
MMC0_DAT1: P02_CM-INTERFACE (J1.27), P04_DEBUG+TF (R70.2 TF_Card.8)
MMC0_DAT2: P02_CM-INTERFACE (J1.28), P04_DEBUG+TF (R55.2 TF_Card.1)
MMC0_DAT3: P02_CM-INTERFACE (J1.29), P04_DEBUG+TF (R56.2 TF_Card.2)
PHY_RX_N: P02_CM-INTERFACE (J1.16), P04_DEBUG+TF (ETHERNET.6)
PHY_RX_P: P02_CM-INTERFACE (J1.14), P04_DEBUG+TF (ETHERNET.3)
PHY_TX_N: P02_CM-INTERFACE (J1.22), P04_DEBUG+TF (ETHERNET.2)
PHY_TX_P: P02_CM-INTERFACE (J1.20), P04_DEBUG+TF (ETHERNET.1)
PWR_BUT: P02_CM-INTERFACE (J1.80), P03_SYSTEM (POWER.1 R41.1 R43.1), P07_EXT-INTERFACE (J4.40)
SPI1_CS0: P02_CM-INTERFACE (J1.55), P06_HDMI (U6.25), P07_EXT-INTERFACE (J4.38)
SPI1_D0: P02_CM-INTERFACE (J1.54), P06_HDMI (U6.24), P07_EXT-INTERFACE (J4.36)
SPI1_D1: P02_CM-INTERFACE (J1.53), P07_EXT-INTERFACE (J4.35)
SPI1_SCLK: P02_CM-INTERFACE (J1.56), P06_HDMI (U6.23), P07_EXT-INTERFACE (J4.37)
SYS_RESETn: P02_CM-INTERFACE (J1.77), P07_EXT-INTERFACE (J4.6)
UART0_RX: P02_CM-INTERFACE (J1.43), P04_DEBUG+TF (R53.2 R54.1), P07_EXT-INTERFACE (J4.24)
UART0_TX: P02_CM-INTERFACE (J1.44), P03_SYSTEM (LED3.2 R19.2), P04_DEBUG+TF (R52.2), P07_EXT-INTERFACE (J4.23)
UART1_RXD: P02_CM-INTERFACE (J1.47), P07_EXT-INTERFACE (J4.28)
UART1_TXD: P02_CM-INTERFACE (J1.48), P07_EXT-INTERFACE (J4.27)
UART2_RXD: P02_CM-INTERFACE (J1.49), P07_EXT-INTERFACE (J4.30)
UART2_TXD: P02_CM-INTERFACE (J1.50), P07_EXT-INTERFACE (J4.29)
USB0_ID: P02_CM-INTERFACE (J2.33), P05_USB_HOST+OTG (ESD1.1 OTG.4)
USB0_N: P02_CM-INTERFACE (J2.34), P05_USB_HOST+OTG (ESD2.1 OTG.2)
USB0_P: P02_CM-INTERFACE (J2.32), P05_USB_HOST+OTG (ESD3.1 OTG.3)
USB1_DRVVBUS: P02_CM-INTERFACE (J2.44), P05_USB_HOST+OTG (R59.1 U2.4)
USB1_ID: P02_CM-INTERFACE (J2.43), P05_USB_HOST+OTG (R57.2)
USB1_N: P02_CM-INTERFACE (J2.42), P05_USB_HOST+OTG (ESD4.1 R49.2)
USB1_P: P02_CM-INTERFACE (J2.40), P05_USB_HOST+OTG (ESD5.1 R48.2)
XDMA_EVENT_INTR0: P02_CM-INTERFACE (J1.85), P06_HDMI (U9.1), P07_EXT-INTERFACE (J4.15)
XDMA_EVENT_INTR1: P02_CM-INTERFACE (J1.87), P07_EXT-INTERFACE (J4.16)
YE_N: P02_CM-INTERFACE (J1.13), P04_DEBUG+TF (ETHERNET.11)
YE_P: P02_CM-INTERFACE (J1.15), P04_DEBUG+TF (ETHERNET.12)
